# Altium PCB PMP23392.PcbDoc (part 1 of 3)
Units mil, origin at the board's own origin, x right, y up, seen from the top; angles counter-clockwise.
Board outline 5000 x 3400 mil, 6 copper layers (Top Layer, Midlayer 1, Midlayer 2, Midlayer 3, Midlayer 4, Bottom Layer), stack 61.536 mil thick; 247 components, 68 nets, 546 pads, 871 vias.
Unrouted connection lines stored in the file: 21.
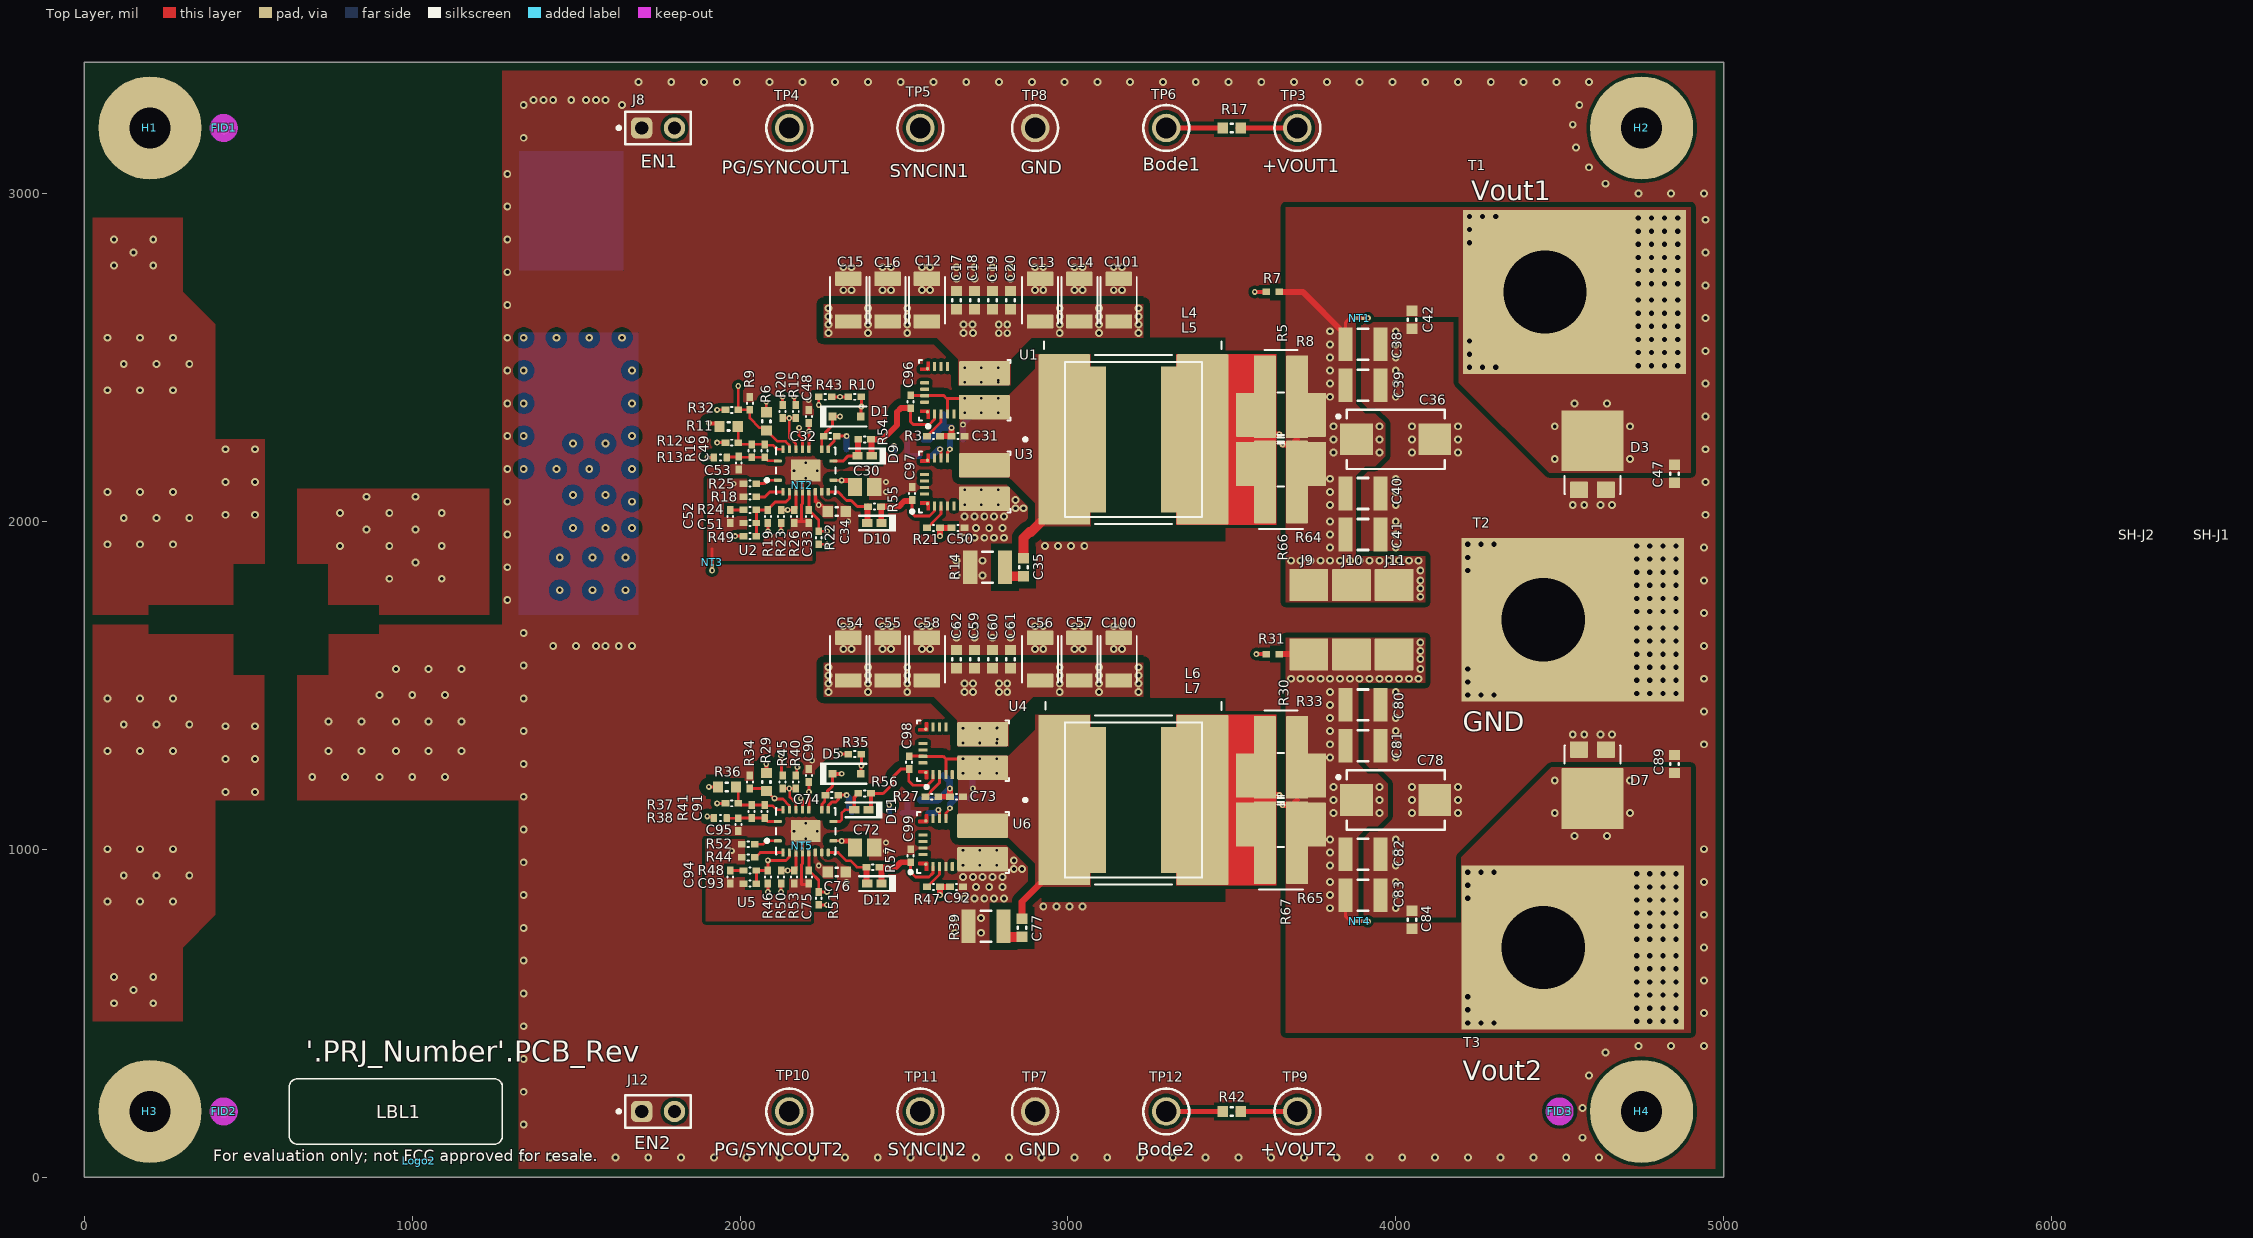
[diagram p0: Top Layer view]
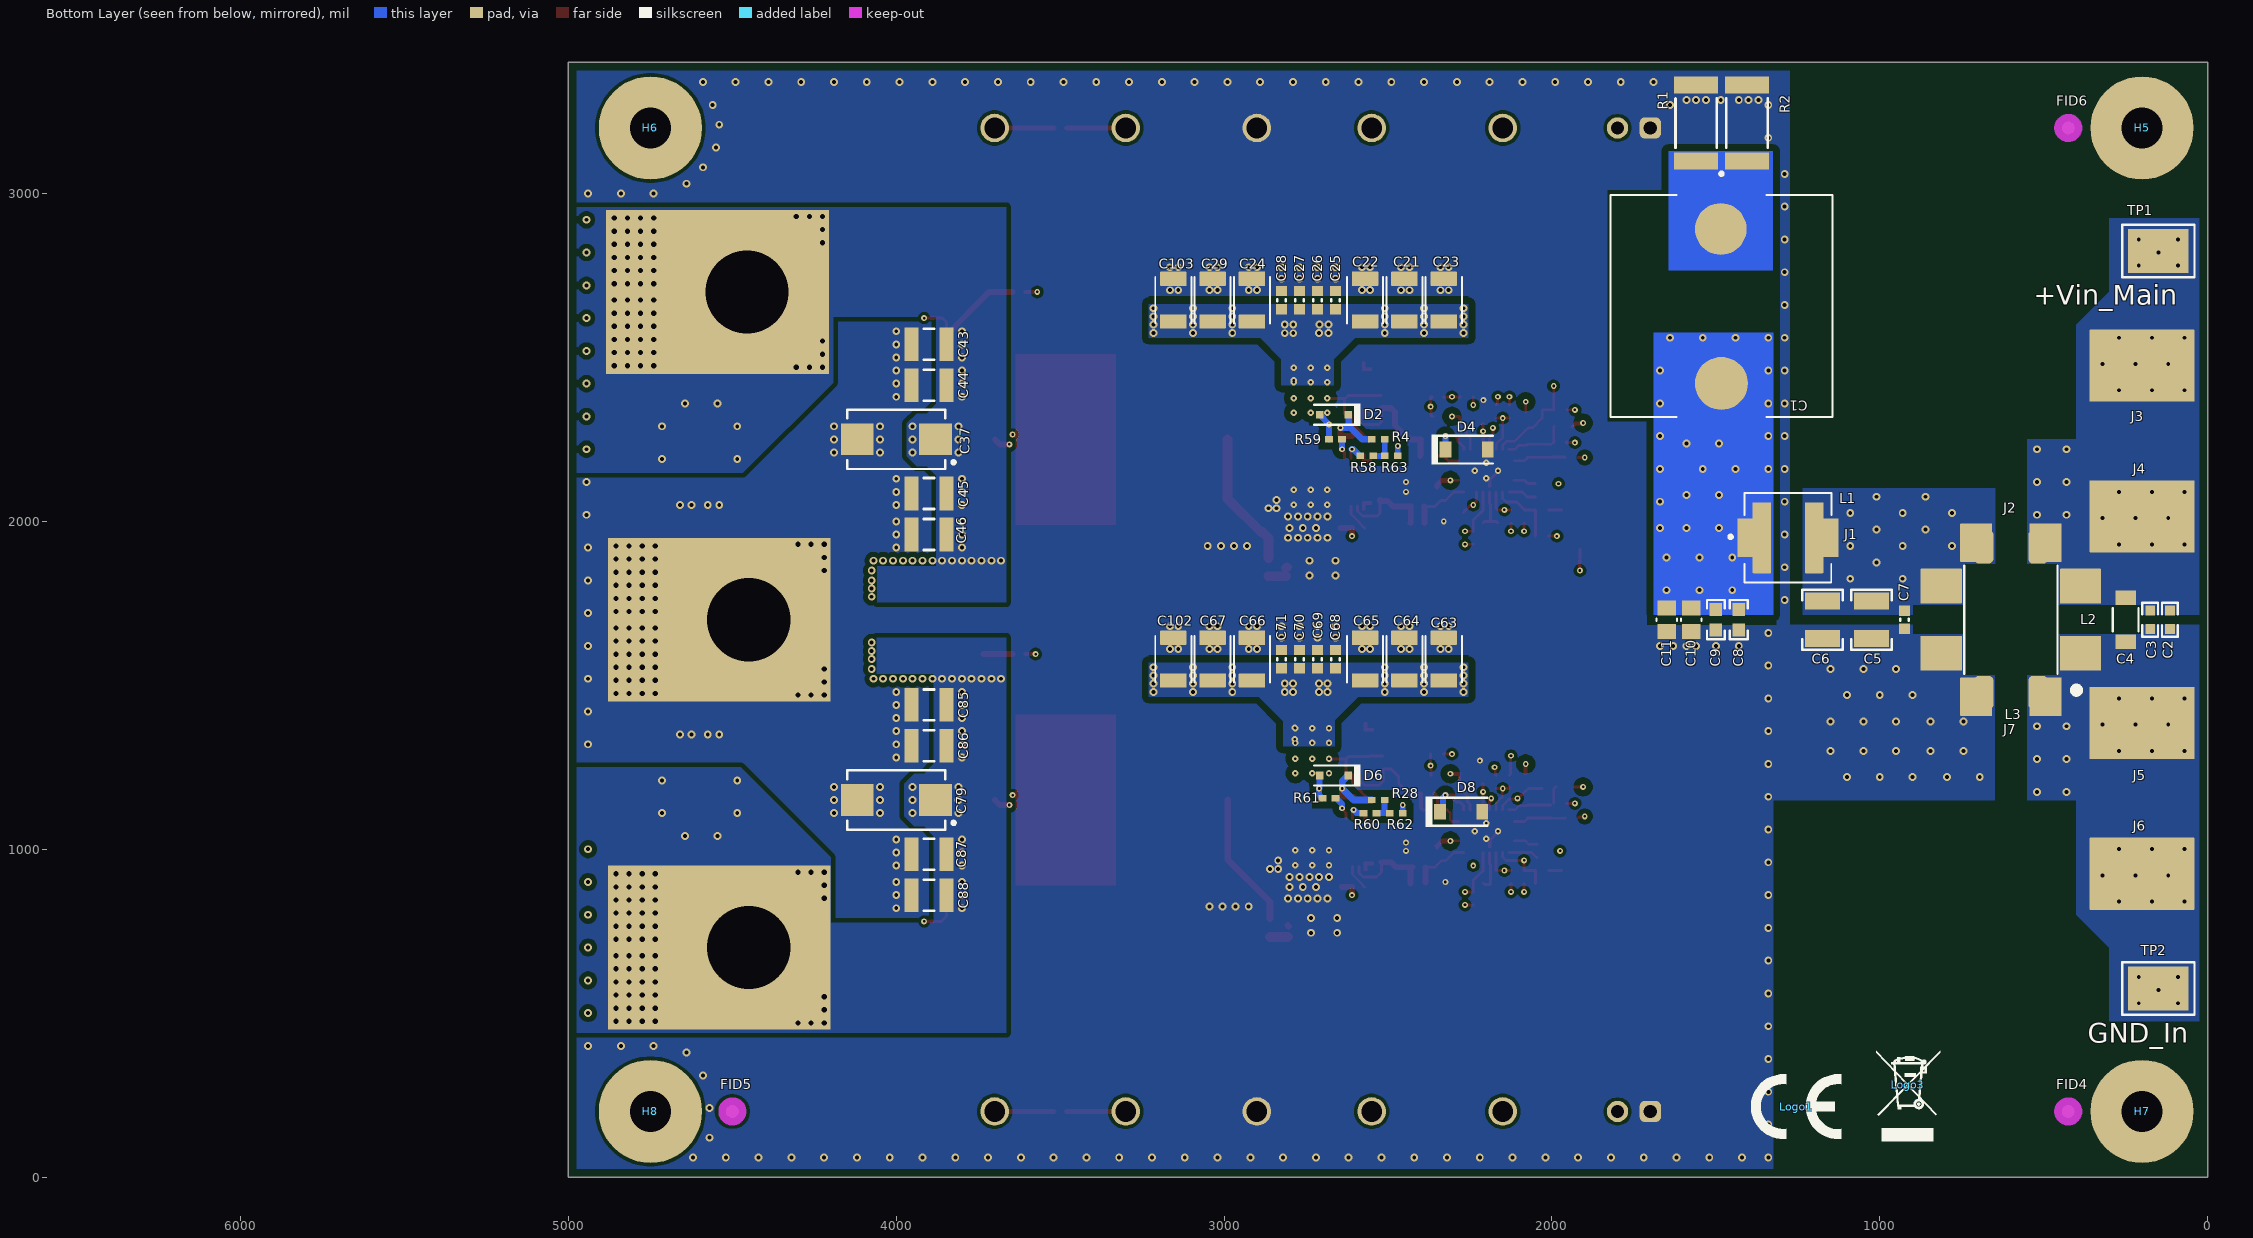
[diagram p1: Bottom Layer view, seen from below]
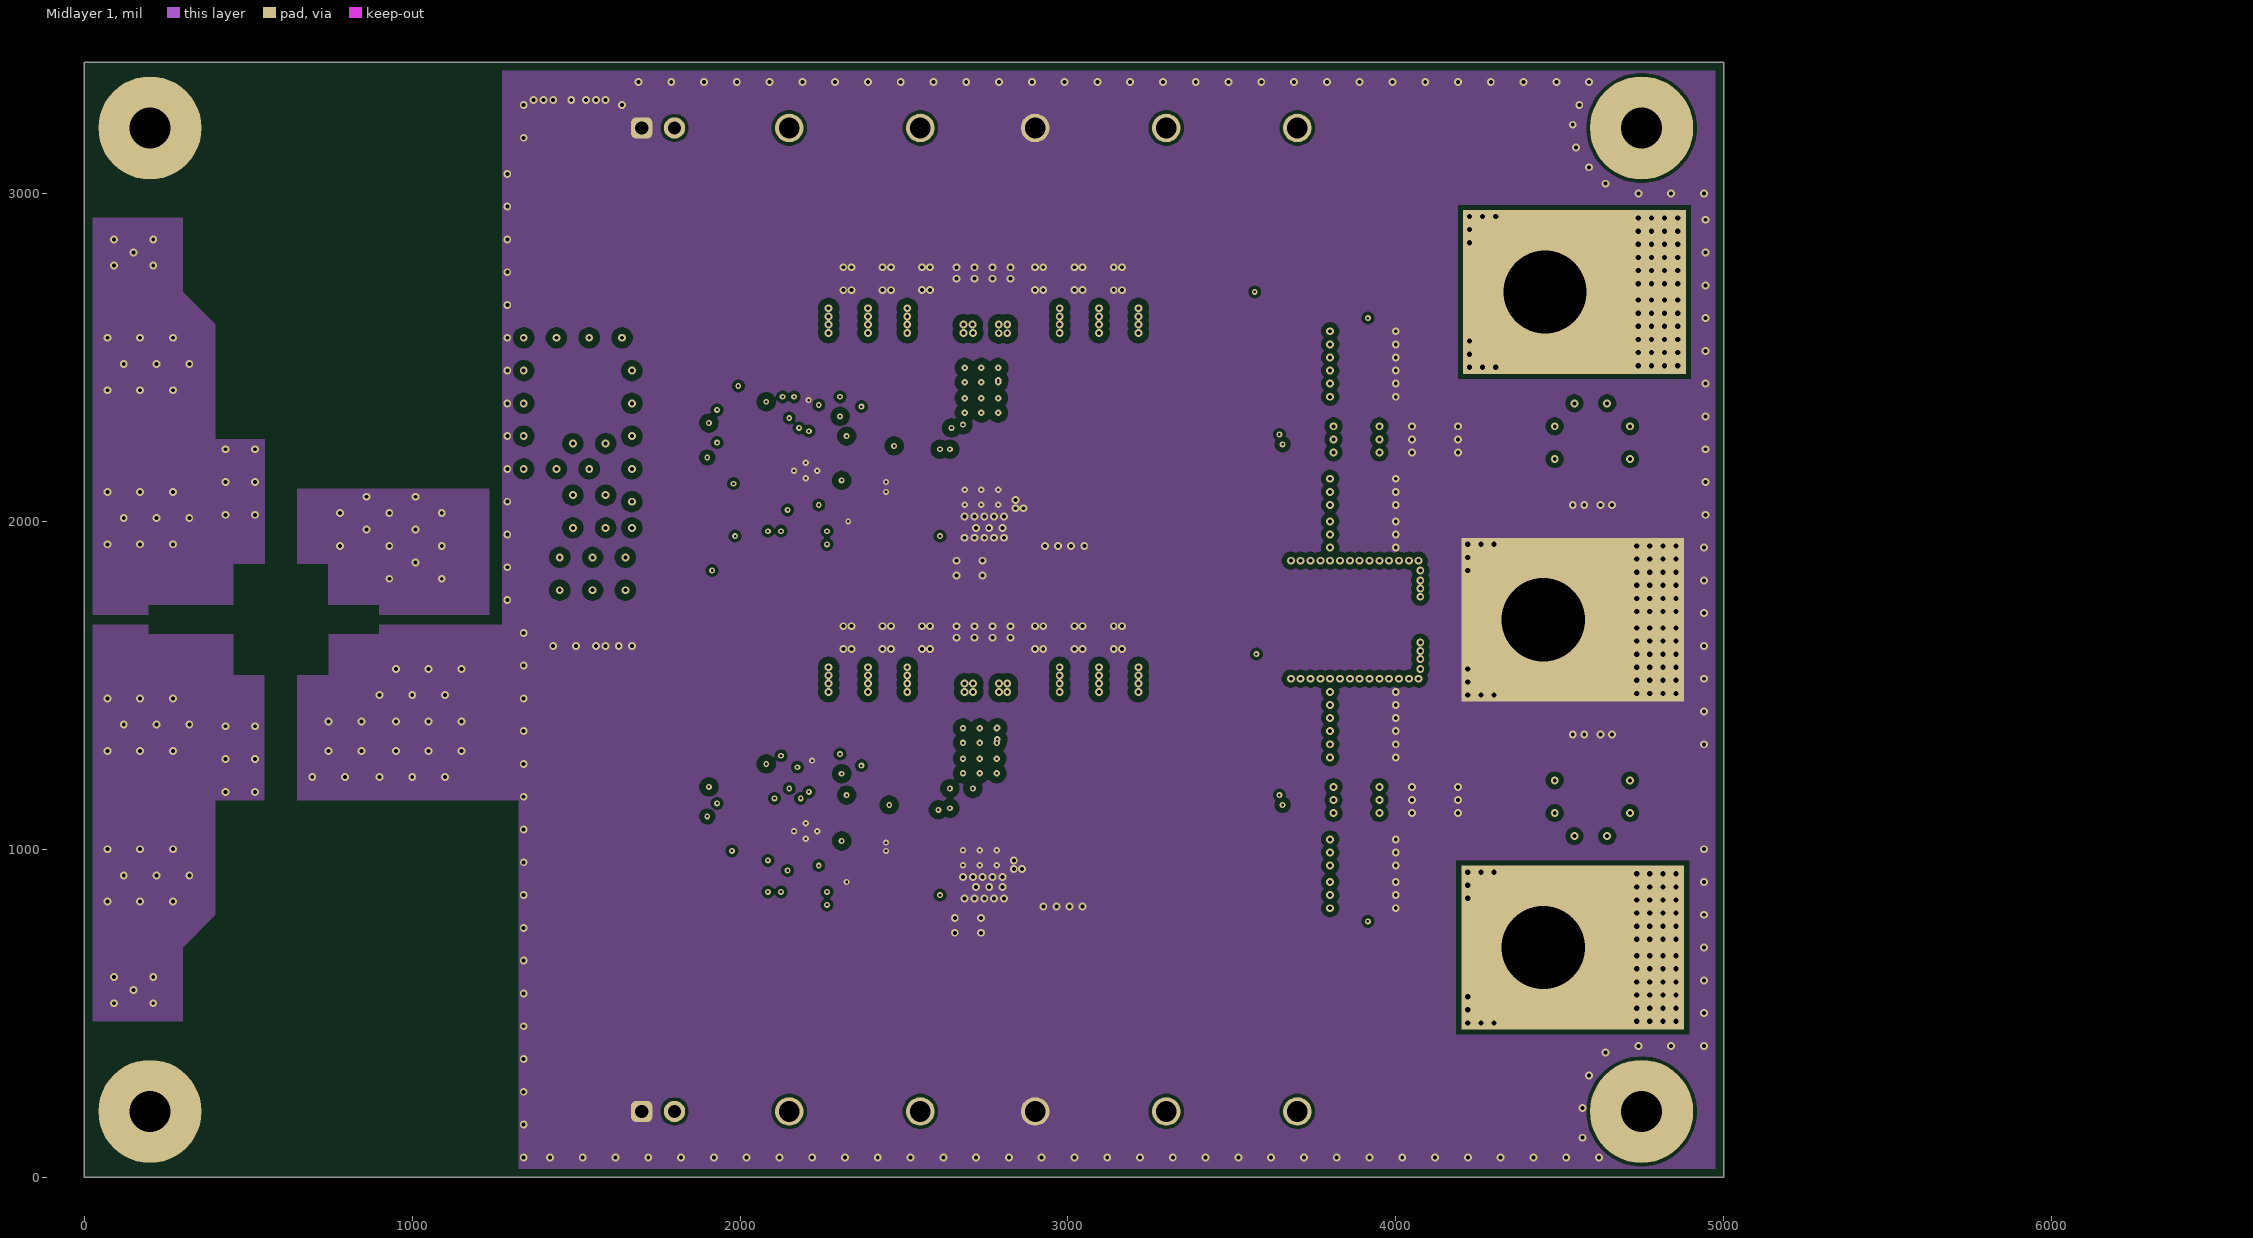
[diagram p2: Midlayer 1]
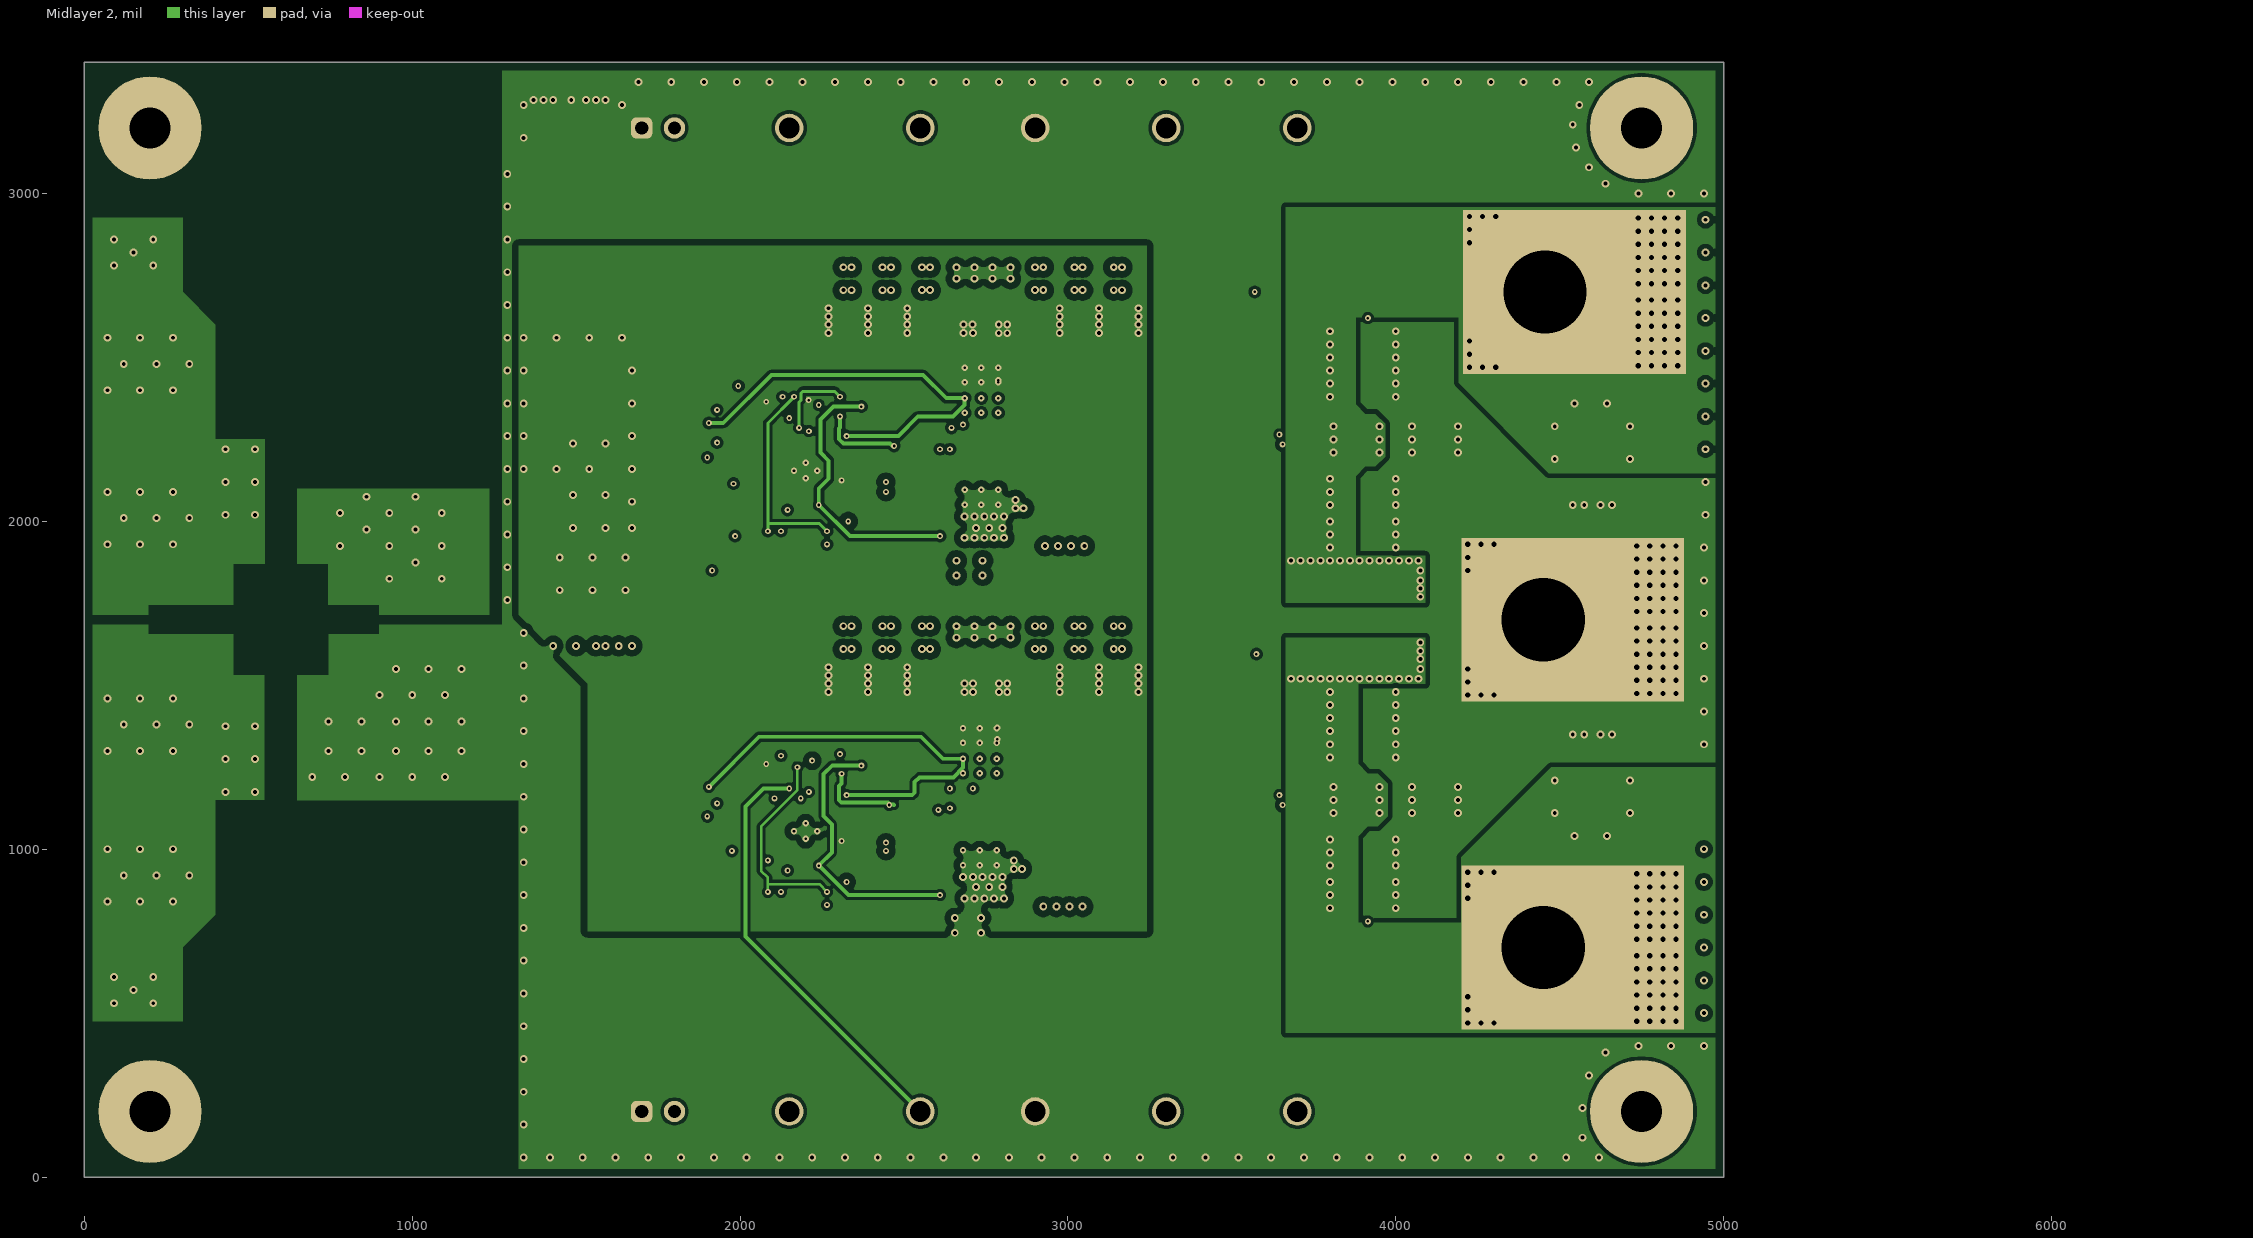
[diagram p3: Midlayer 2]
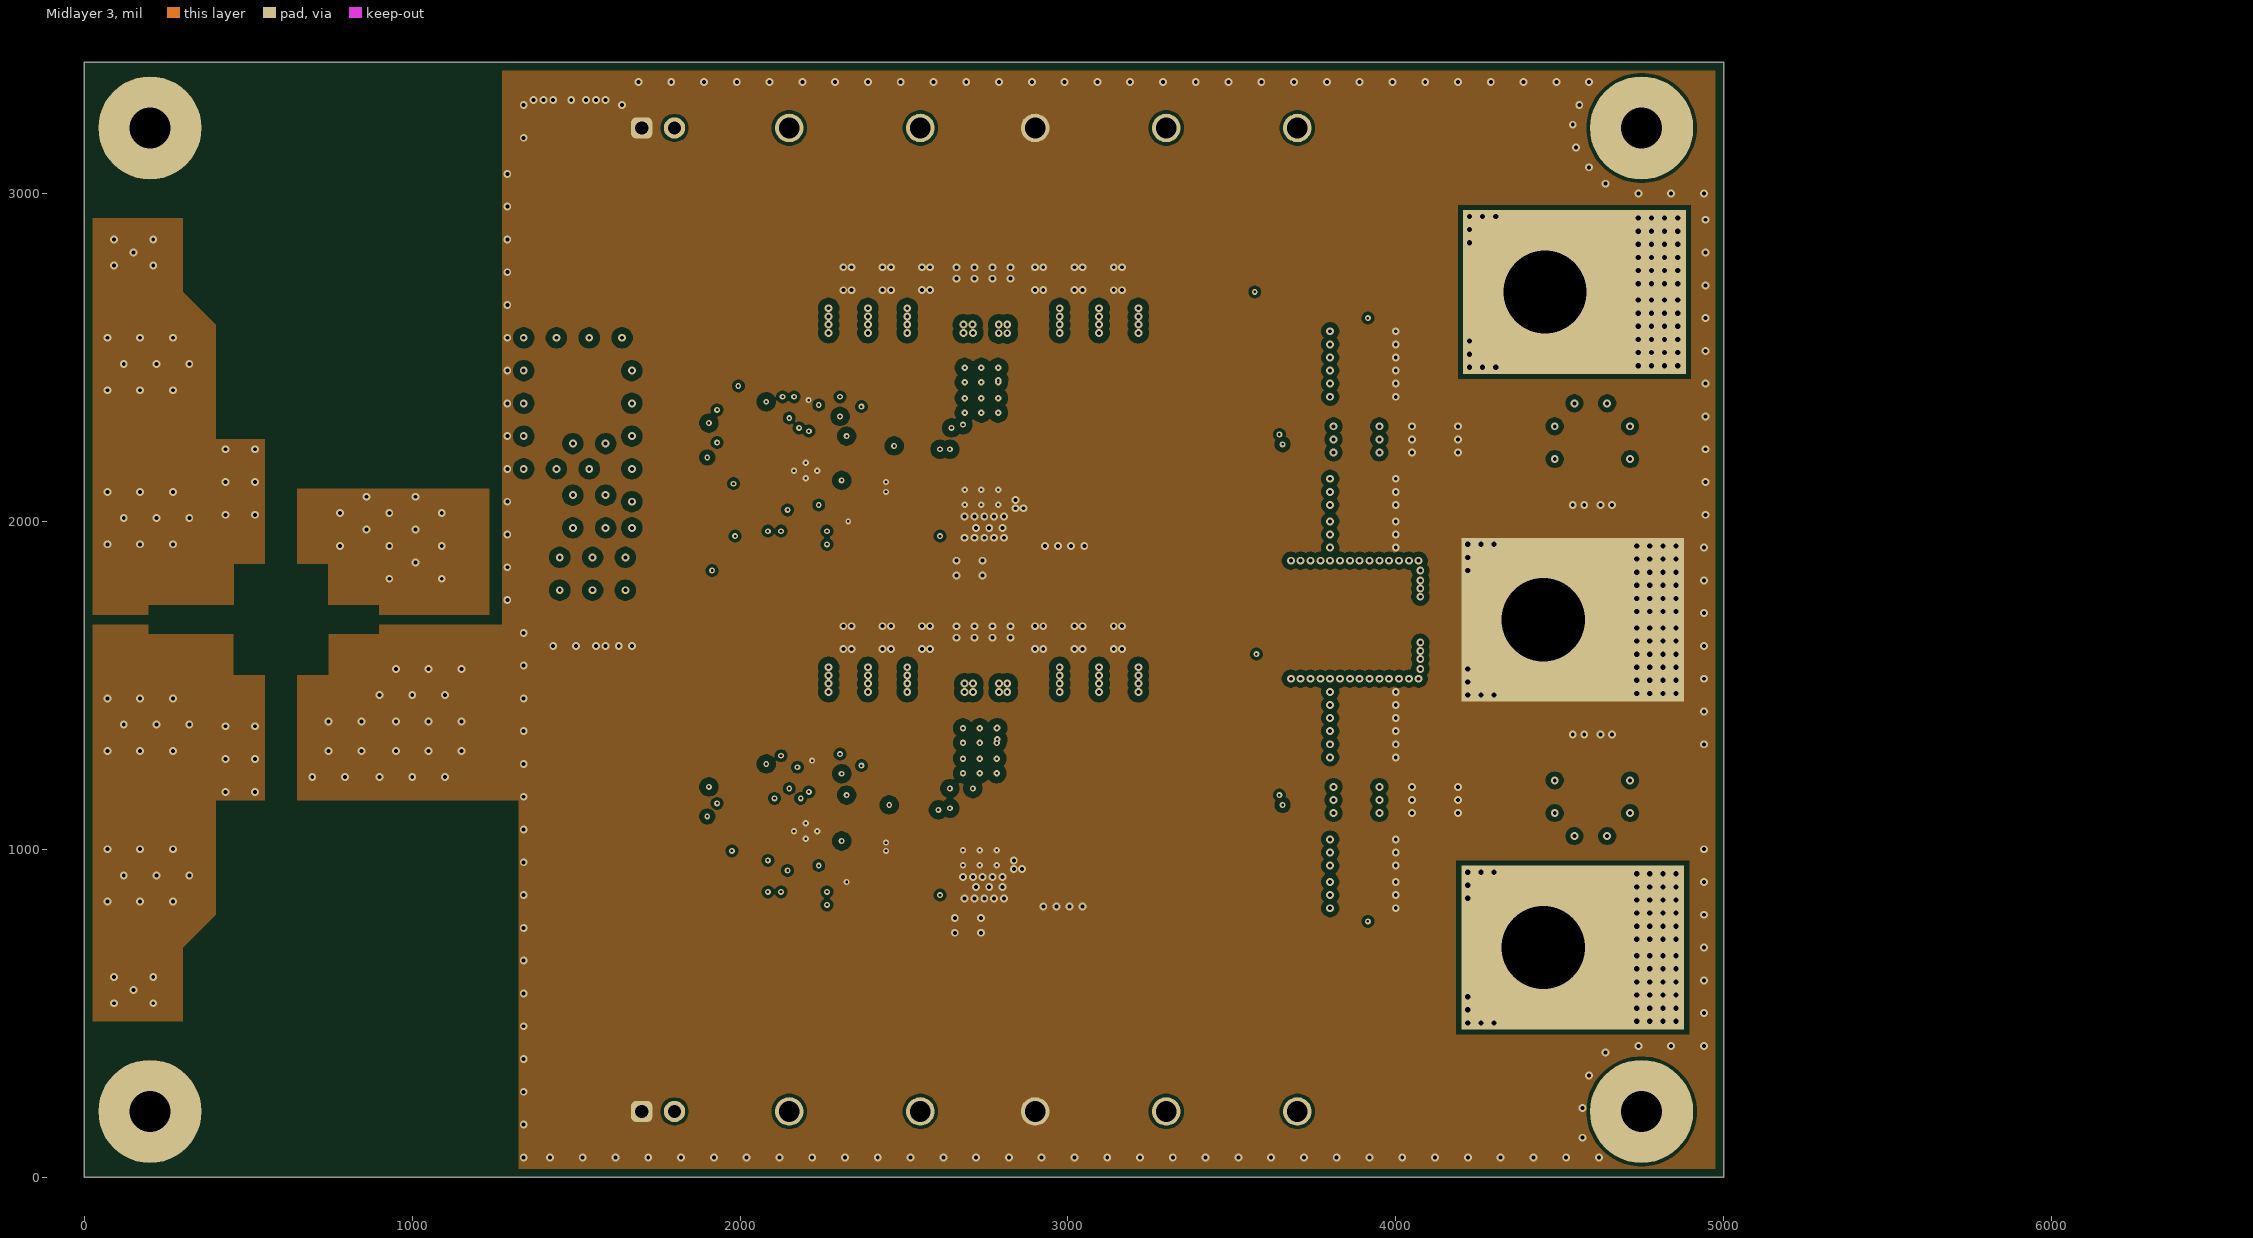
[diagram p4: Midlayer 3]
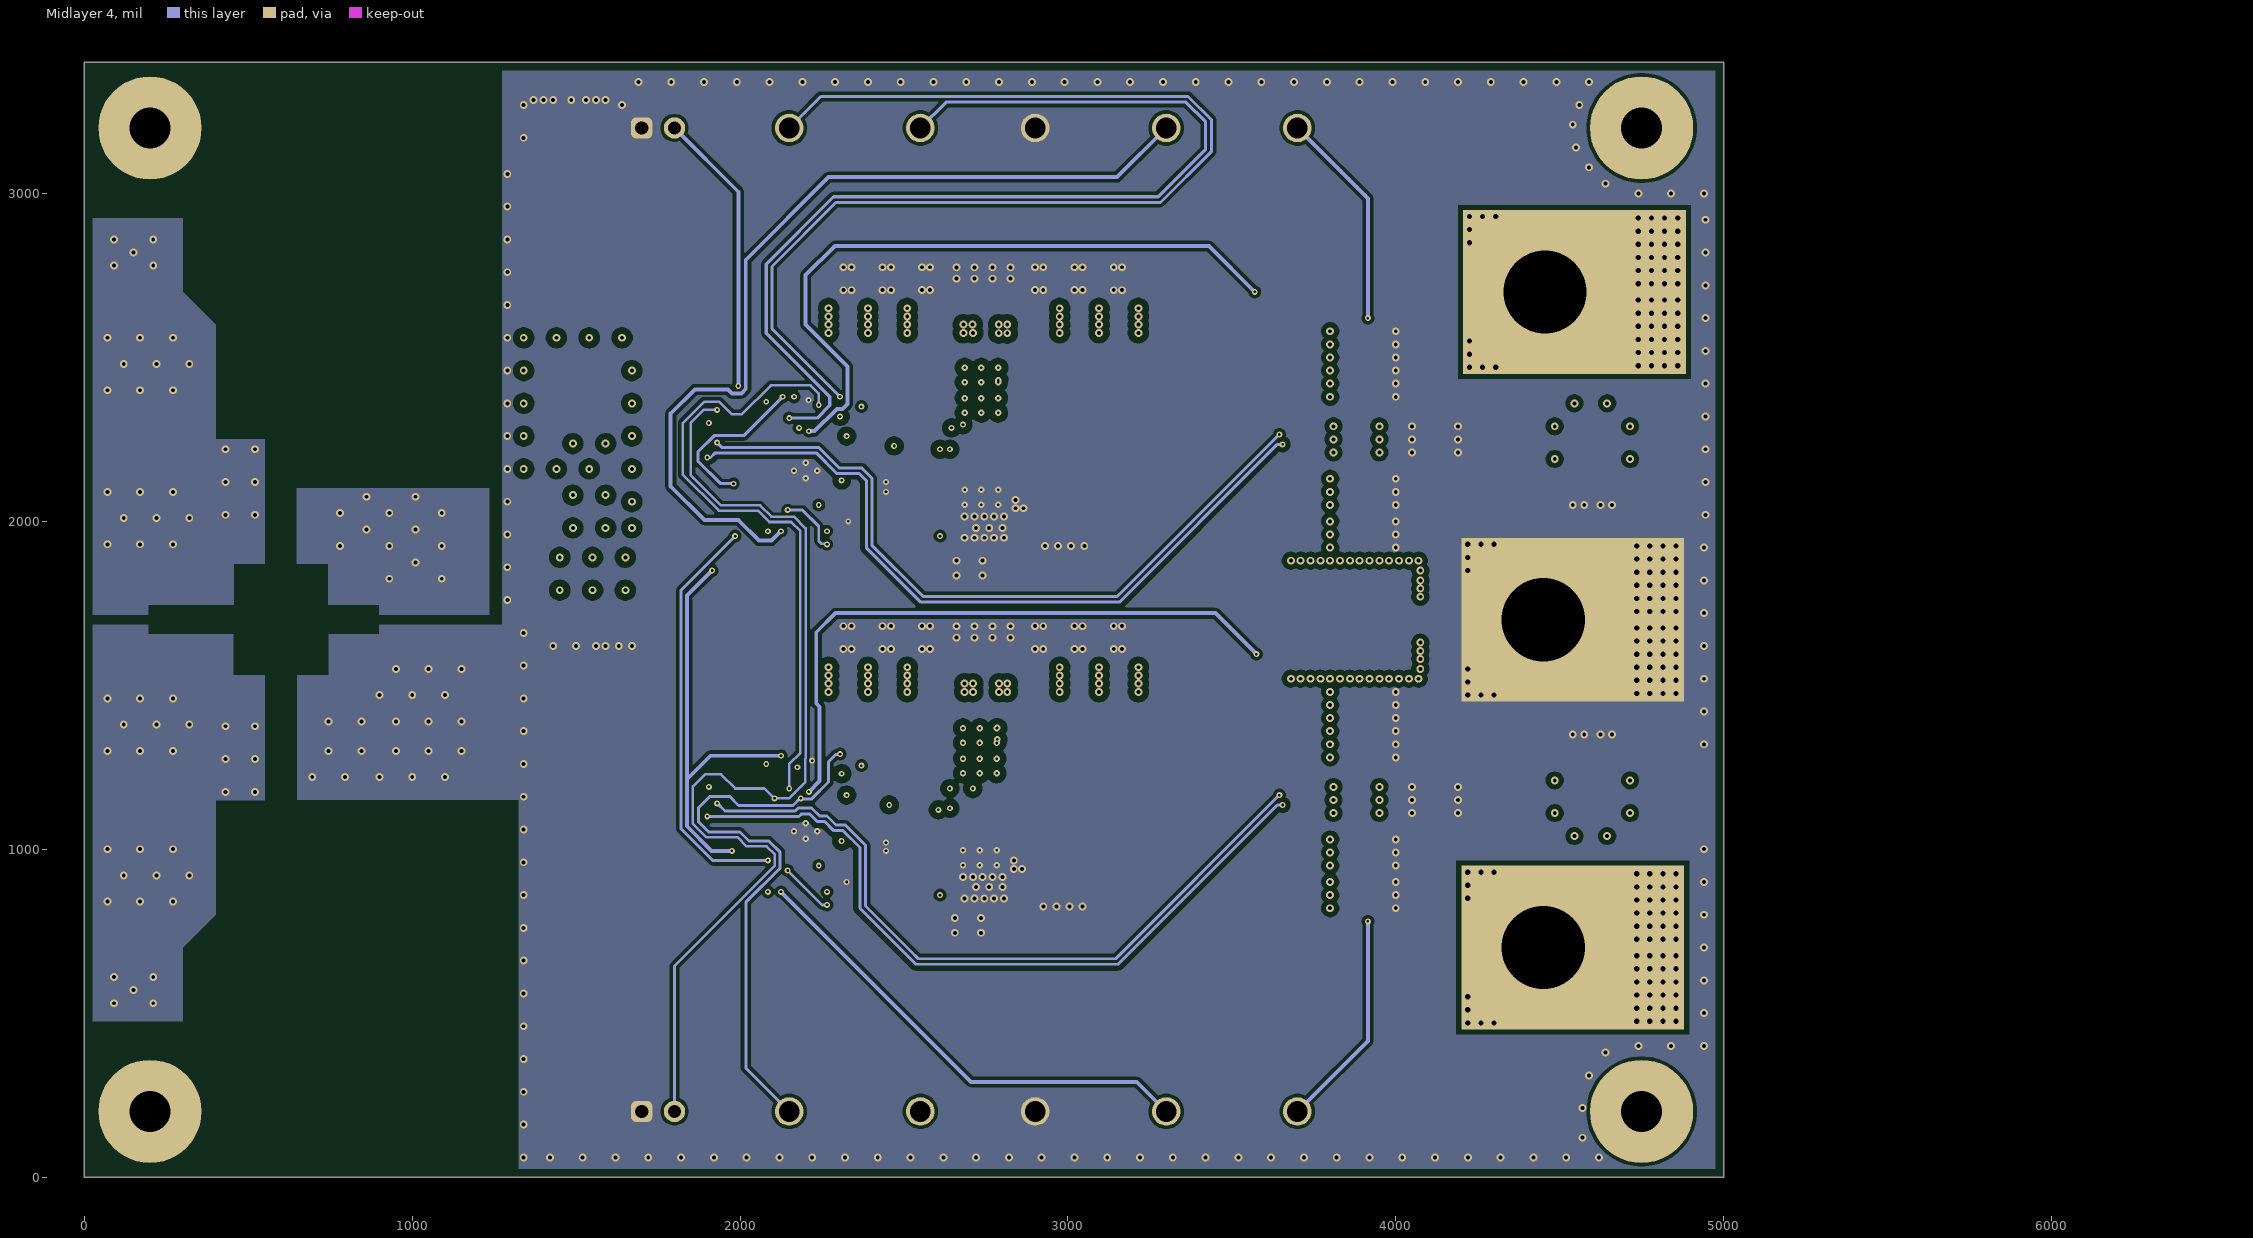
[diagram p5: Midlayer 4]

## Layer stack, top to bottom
Top Solder: solder mask 0.4, Solder Resist, Dk 3.5
Top Layer: signal copper 2.756
Dielectric 1: prepreg 9, PP-023, Dk 4.5
Midlayer 1: signal copper 2.7559
Dielectric 2: prepreg 9, PP-023, Dk 4.5
Midlayer 2: signal copper 2.7559
Dielectric3: core 9, Core-034, Dk 4.6
Midlayer 3: signal copper 2.7559
Dielectric 4: prepreg 9, PP-023, Dk 4.5
Midlayer 4: signal copper 2.7559
Dielectric 5: prepreg 9, PP-023, Dk 4.5
Bottom Layer: signal copper 2.756
Bottom Solder: solder mask 0.4, Solder Resist, Dk 3.5

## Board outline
0,0 5000,0 5000,3400 0,3400

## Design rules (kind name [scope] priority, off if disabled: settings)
AcuteAngle [All] p1: minimum=4.50000000000000E+0001 checktracksonly=FALSE
AssemblyTestPointUsage [All] p1: valid=2
BoardOutlineClearance BoardOutlineClearance_MountingHoles [OnCopper and InComponentClass('Mounting Holes')] p1: gap=39.37 ignorepadtopadclearanceinfootprint=FALSE
BoardOutlineClearance BoardOutlineClearance_Poly [OnCopper and IsPoly] p2: gap=25 ignorepadtopadclearanceinfootprint=FALSE
BoardOutlineClearance [OnCopper and Not InComponentClass('Logo') and not InComponentClass('FiducialMark') and not InRegion(1000,500,4000,800) and not InPoly] p3: gap=40 ignorepadtopadclearanceinfootprint=FALSE
Clearance Clearance_HV [InNetClass('HV') vs InNet('GND')] p1: gap=20 ignorepadtopadclearanceinfootprint=TRUE
Clearance Clearance_VOUT [(InNet('VOUT1') OR InNet('VOUT2')) vs InNet('GND')] p2: gap=15 ignorepadtopadclearanceinfootprint=TRUE
Clearance Clearance_Keepouts [((IsTrack Or IsArc) And Not InPoly) And IsFree and IsKeepOut vs ((IsTrack Or IsArc) And Not InPoly) And IsFree and IsKeepOut] p3: gap=0 ignorepadtopadclearanceinfootprint=FALSE
Clearance Clearance_Poly [InPolygon] p4: gap=10 ignorepadtopadclearanceinfootprint=TRUE
Clearance Clearance_FiducialMark [IsKeepOut and InComponentClass('FiducialMark') vs IsPad and InComponentClass('FiducialMark')] p5: gap=0 ignorepadtopadclearanceinfootprint=FALSE
Clearance [All] p6: gap=7.87 ignorepadtopadclearanceinfootprint=TRUE
ComponentClearance ComponentClearance_L3,J2 [InComponent('L3') vs InComponent('J2')] p1: gap=-1 collisioncheckmode=3 verticalgap=100000 showdistances=FALSE
ComponentClearance "ComponentClearance_L1, J1" [InComponent('L1') vs InComponent('J1')] p2: gap=-1 collisioncheckmode=3 verticalgap=100000 showdistances=FALSE
ComponentClearance "ComponentClearance_L2, J2" [InComponent('L2') vs InComponent('J2')] p3: gap=-1 collisioncheckmode=3 verticalgap=100000 showdistances=FALSE
ComponentClearance "ComponentClearance_L3, J7" [InComponent('L3') vs InComponent('J7')] p4: gap=-1 collisioncheckmode=3 verticalgap=100000 showdistances=FALSE
ComponentClearance "ComponentClearance_L2, J7" [InComponent('L2') vs InComponent('J7')] p5: gap=-1 collisioncheckmode=3 verticalgap=100000 showdistances=FALSE
ComponentClearance "ComponentClearance_L2, J4" [InComponent('L2') vs InComponent('J4')] p6: gap=-1 collisioncheckmode=3 verticalgap=100000 showdistances=FALSE
ComponentClearance ComponentClearance_L2,L3 [InComponent('L2') vs InComponent('L3')] p7: gap=-1 collisioncheckmode=3 verticalgap=100000 showdistances=FALSE
ComponentClearance "ComponentClearance_NT5, U5" [InComponent('NT5') vs InComponent('U5')] p8: gap=-1 collisioncheckmode=3 verticalgap=100000 showdistances=FALSE
ComponentClearance "ComponentClearance_NT2, U2" [InComponent('NT2') vs InComponent('U2')] p9: gap=-1 collisioncheckmode=3 verticalgap=100000 showdistances=FALSE
ComponentClearance ComponentClearance_R5,R8 [InComponent('R5') vs InComponent('R8')] p10: gap=-1 collisioncheckmode=3 verticalgap=100000 showdistances=FALSE
ComponentClearance ComponentClearance_R5,R66 [InComponent('R5') vs InComponent('R66')] p11: gap=-1 collisioncheckmode=3 verticalgap=100000 showdistances=FALSE
ComponentClearance "ComponentClearance_R8, R66" [InComponent('R8') vs InComponent('R66')] p12: gap=-1 collisioncheckmode=3 verticalgap=100000 showdistances=FALSE
ComponentClearance ComponentClearance_R5,R64 [InComponent('R5') vs InComponent('R64')] p13: gap=-1 collisioncheckmode=3 verticalgap=100000 showdistances=FALSE
ComponentClearance "ComponentClearance_R64, R66" [InComponent('R64') vs InComponent('R66')] p14: gap=-1 collisioncheckmode=3 verticalgap=100000 showdistances=FALSE
ComponentClearance "ComponentClearance_L4, L5" [(InComponent('L4') OR InComponent('L5'))] p15: gap=-1 collisioncheckmode=3 verticalgap=100000 showdistances=FALSE
ComponentClearance "ComponentClearance_L6, L7" [(InComponent('L6') OR InComponent('L7'))] p16: gap=-1 collisioncheckmode=3 verticalgap=100000 showdistances=FALSE
ComponentClearance ComponentClearance_R30,R33 [InComponent('R30') vs InComponent('R33')] p17: gap=-1 collisioncheckmode=3 verticalgap=100000 showdistances=FALSE
ComponentClearance "ComponentClearance_R33, R67" [InComponent('R33') vs InComponent('R67')] p18: gap=-1 collisioncheckmode=3 verticalgap=100000 showdistances=FALSE
ComponentClearance ComponentClearance_R30,R65 [InComponent('R30') vs InComponent('R65')] p19: gap=-1 collisioncheckmode=3 verticalgap=100000 showdistances=FALSE
ComponentClearance ComponentClearance_R30,R67 [InComponent('R30') vs InComponent('R67')] p20: gap=-1 collisioncheckmode=3 verticalgap=100000 showdistances=FALSE
ComponentClearance "ComponentClearance_R65, R67" [InComponent('R65') vs InComponent('R67')] p21: gap=-1 collisioncheckmode=3 verticalgap=100000 showdistances=FALSE
ComponentClearance ComponentClearance_MountingHoles_FiducialMarks [InComponentClass('Mounting Holes') vs InComponentClass('FiducialMark')] p22: gap=50 collisioncheckmode=3 verticalgap=10 showdistances=FALSE
ComponentClearance ComponentClearance_Shunt [InComponentClass('Header') vs InComponentClass('Shunt')] p23: gap=0 collisioncheckmode=3 verticalgap=0 showdistances=FALSE
ComponentClearance ComponentClearance_Logo [InComponentClass('Logo')] p24: gap=30 collisioncheckmode=3 verticalgap=10 showdistances=FALSE
ComponentClearance ComponentClearance_ScrewToNut [(HasFootprint('NY PMS 440 0025 PH')) vs (HasFootprint('Keystone_1902C'))] p25: gap=5 collisioncheckmode=3 verticalgap=10 showdistances=FALSE
ComponentClearance ComponentClearance_MountingHoles [InComponentClass('Mounting Holes')] p26: gap=100 collisioncheckmode=3 verticalgap=100000 showdistances=FALSE
ComponentClearance ComponentClearance_SmallPassives [HasFootprint('0201*') or HasFootprint('0402*') or HasFootprint('0508') or HasFootprint('0603*') or HasFootprint('0612') or HasFootprint('0805*') or HasFootprint('0815*') or HasFootprint('0830*') or HasFootprint('1206*') or HasFootprint('1210*') or HasFootprint('1808*') or HasFootprint('1812*') or HasFootprint('1825*') or HasFootprint('2010*') or HasFootprint('2220*') or HasFootprint('2225*') or HasFootprint('2512*') or HasFootprint('2728*') or HasFootprint('3518*') vs HasFootprint('0201*') or HasFootprint('0402*') or HasFootprint('0508') or HasFootprint('0603*') or HasFootprint('0612') or HasFootprint('0805*') or HasFootprint('0815*') or HasFootprint('0830*') or HasFootprint('1206*') or HasFootprint('1210*') or HasFootprint('1808*') or HasFootprint('1812*') or HasFootprint('1825*') or HasFootprint('2010*') or HasFootprint('2220*') or HasFootprint('2225*') or HasFootprint('2512*') or HasFootprint('2728*') or HasFootprint('3518*')] p27: gap=14.96 collisioncheckmode=3 verticalgap=10 showdistances=FALSE
ComponentClearance ComponentClearance_THtoSMT [IsThruComponent vs IsSMTComponent] p28: gap=30 collisioncheckmode=3 verticalgap=30 showdistances=FALSE
ComponentClearance ComponentClearance_THtoTH [IsThruComponent vs IsThruComponent] p29: gap=20 collisioncheckmode=3 verticalgap=30 showdistances=FALSE
ComponentClearance [All] p30: gap=20 collisioncheckmode=3 verticalgap=10 showdistances=FALSE
DiffPairsRouting [All] p1: maxlimit=100 minlimit=10 mostfreqgap=10 toplayer_minwidth=15 toplayer_maxwidth=15 toplayer_prefwidth=15 midlayer1_minwidth=15 midlayer1_maxwidth=15 midlayer1_prefwidth=15 midlayer2_minwidth=15 midlayer2_maxwidth=15 midlayer2_prefwidth=15 midlayer3_minwidth=15 midlayer3_maxwidth=15 midlayer3_prefwidth=15 midlayer4_minwidth=15 midlayer4_maxwidth=15 midlayer4_prefwidth=15 bottomlayer_minwidth=15 bottomlayer_maxwidth=15 bottomlayer_prefwidth=15 maxuncoupledlength=1000
FabricationTestPointUsage TestPointUsage [All] p1: valid=2 allowmultiple=FALSE
FabricationTestpoint Testpoint [All] p1: side=3 testpointundercomponent=TRUE minsize=40 maxsize=100 preferedsize=60 minholesize=0 maxholesize=40 preferedholesize=32 testpointgrid=1 allowsidetop=TRUE allowsidebottom=TRUE usegrid=TRUE gridtolerance=0.01
FanoutControl Fanout_LCC [IsLCC] p1: bgadir=Out bgaviamode=Centered fanoutstyle=Auto fanoutdirection=Alternating viagrid=1 // Fanout_LCC (Default Rule)
FanoutControl Fanout_BGA [IsBGA] p2: bgadir=Out bgaviamode=Centered fanoutstyle=Auto fanoutdirection=Alternating viagrid=1 // Fanout_BGA (Default Rule)
FanoutControl Fanout_Default [All] p4: bgadir=Out bgaviamode=Centered fanoutstyle=Auto fanoutdirection=Alternating viagrid=1 // Fanout_Default (Default Rule)
FanoutControl Fanout_Small [(CompPinCount < 5)] p5: bgadir=Out bgaviamode=Centered fanoutstyle=Auto fanoutdirection=OutThenIn viagrid=1 // Fanout_Small (Default Rule)
HoleSize [All] p1: absolutevalues=TRUE maxlimit=255 minlimit=7.87 maxpercent=80.000 minpercent=20.000
MinimumAnnularRing MinimumAnnularRing_ThermalPadVias [IsVia and InAnyComponent] p1: minimumring=5.91
MinimumAnnularRing [All] p2: minimumring=5
MinimumSolderMaskSliver MinimumSolderMaskSliver_Logo [InComponentClass('Logo') vs InComponentClass('Logo')] p1: minsoldermaskwidth=0.7
MinimumSolderMaskSliver [All] p2: minsoldermaskwidth=3.94
PlaneConnect [All] p1: planeconnectstyle=Direct reliefexpansion=10 reliefentries=4 reliefconductorwidth=10 reliefairgap=10
PolygonConnect [All] p1: connectstyle=Direct reliefconductorwidth=10 reliefentries=4 polygonreliefangle="90 Angle" airgapwidth=10
RoutingVias ThermalPadVias [IsVia and InAnyComponent] p1: holewidth=7.87 width=19.68 viastyle="Through Hole" minholewidth=7.87 minwidth=18 maxholewidth=40 maxwidth=50
RoutingVias [All] p2: holewidth=16 width=34 viastyle="Through Hole" minholewidth=7.87 minwidth=18 maxholewidth=40 maxwidth=65
SilkToBoardRegionClearance [Not ((IsComment or IsDesignator) And (Hide <> 'False')) and not InRegion(1000,500,4000,800)] p1:
SilkToSilkClearance SilkToSilkClearance_Pb-FreeLogo [(HasFootprint('Pb-Free_Overlay_Medium') OR HasFootprint('Pb-Free_Overlay_Small')) vs (HasFootprint('Pb-Free_Overlay_Medium') OR HasFootprint('Pb-Free_Overlay_Small'))] p1: silktosilkclearance=0
SilkToSilkClearance [All] p2: silktosilkclearance=1
SilkToSolderMaskClearance SilkToComponentPadClearance [(IsPad or IsFill or IsRegion) and InAnycomponent] p1: minsilkscreentomaskgap=2 clearancetoexposedcopper=TRUE
SilkToSolderMaskClearance "Silk to Solder Mask Opening" [All] p2: minsilkscreentomaskgap=2 clearancetoexposedcopper=FALSE
SolderMaskExpansion [All] p1: expansion=1.97 istentingtop=FALSE
UnRoutedNet [All] p1: checkbadconnections=TRUE
Width [All] p1: maxlimit=100 minlimit=6 preferedwidth=10 checkconnectedcopper=TRUE
14 further rules are at their usual default settings.

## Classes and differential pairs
net class HV: +Filter +Vin_Main HO1 HO1_GAN HO2 HO2_GAN NetC1_1 NetC31_1 NetC35_2 NetC73_1 NetC77_2 NetR3_2 NetR4_2 NetR27_2 NetR28_2 NetR58_1 NetR59_1 NetR60_1 NetR61_1 SW1 SW2 Vbst1 Vbst2 VIN
component class Shunt: SH-J1 SH-J2
component class PMP23392_BlankSheet: C1 C2 C3 C4 C5 C6 C7 C8 C9 C10 C11 C12 C13 C14 C15 C16 C17 C18 C19 C20 C21 C22 C23 C24 C25 C26 C27 C28 C29 C30 C31 C32 C33 C34 C35 C36 C37 C38 C39 C40 C41 C42 C43 C44 C45 C46 C47 C48 C49 C50 C51 C52 C53 C54 C55 C56 C57 C58 C59 C60 C61 C62 C63 C64 C65 C66 C67 C68 C69 C70 C71 C72 C73 C74 C75 C76 C77 C78 C79 C80 C81 C82 C83 C84 C85 C86 C87 C88 C89 C90 C91 C92 C93 C94 C95 C96 C97 C98 C99 C100 C101 C102 C103 D1 D2 D3 D4 D5 D6 D7 D8 D9 D10 D11 D12 J1 J2 J3 J4 J5 J6 J7 J8 J9 J10 J11 J12 L1 L2 L3 L4 L5 L6 L7 NT1 NT2 NT3 NT4 NT5 R1 R2 R3 R4 R5 R6 R7 R8 R9 R10 R11 R12 R13 R14 R15 R16 R17 R18 R19 R20 R21 R22 R23 R24 R25 R26 R27 R28 R29 R30 R31 R32 R33 R34 R35 R36 R37 R38 R39 R40 R41 R42 R43 R44 R45 R46 R47 R48 R49 R50 R51 R52 R53 R54 R55 R56 R57 R58 R59 R60 R61 R62 R63 R64 R65 R66 R67 SH-J1 SH-J2 T1 T2 T3 TP1 TP2 TP3 TP4 TP5 TP6 TP7 TP8 TP9 TP10 TP11 TP12 U1 U2 U3 U4 U5 U6
component class Header: J8 J12
component class Label: LBL1
component class FiducialMark: FID1 FID2 FID3 FID4 FID5 FID6
component class PMP23392_Hardware: FID1 FID2 FID3 FID4 FID5 FID6 H1 H2 H3 H4 H5 H6 H7 H8 LBL1 Logo1 Logo2 Logo3
component class "Mounting Holes": H1 H2 H3 H4

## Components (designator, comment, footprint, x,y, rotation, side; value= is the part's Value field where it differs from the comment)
C1 "EEE-TP1K391V" FP-EEE-TP1K391V_SMT_CAP_17MM0_17MM0-MFG 1483,2657 r270 bottom value=390µF
C2 "GCM188R72A103KA37J" 0603_HV 115,1700 r270 bottom value=0.01uF
C3 "GCM188R72A103KA37J" 0603_HV 175,1700 r270 bottom value=0.01uF
C4 "CGA5L3X7S2A225K160AB" 1206_180 250,1700 r270 bottom value=2.2uF
C5 "C3225X7S2A475K200AB" 1210_220 1025,1700 r90 bottom value=4.7uF
C6 "CGA6M3X7S2A475K200AB" 1210_220 1175,1700 r90 bottom value=4.7uF
C7 "GCM188R72A103KA37J" 0603L 925,1700 r270 bottom value=0.01uF
C8 "GCM188R72A103KA37J" 0603 1430,1700 r270 bottom value=0.01uF
C9 "GCM188R72A103KA37J" 0603 1500,1700 r270 bottom value=0.01uF
C10 "08051C105K4Z2A" 0805_150 1575,1700 r270 bottom value=1uF
C11 "08051C105K4Z2A" 0805_150 1650,1700 r270 bottom value=1uF
C12 "GCJ32DC72A475KE01L" FP-GCJ32DC72A475KE01L_1210-MFG 2570,2675 r270 top value=4.7µF
C13 "GCJ32DC72A475KE01L" FP-GCJ32DC72A475KE01L_1210-MFG 2915,2675 r270 top value=4.7µF
C14 "GCJ32DC72A475KE01L" FP-GCJ32DC72A475KE01L_1210-MFG 3035,2675 r270 top value=4.7µF
C15 "GCJ32DC72A475KE01L" FP-GCJ32DC72A475KE01L_1210-MFG 2330,2675 r270 top value=4.7µF
C16 "GCJ32DC72A475KE01L" FP-GCJ32DC72A475KE01L_1210-MFG 2450,2675 r270 top value=4.7µF
C17 "GCJ188R72A104KA01D" 0603L 2660,2675 r90 top value=0.1uF
C18 "GCJ188R72A104KA01D" 0603L 2715,2675 r90 top value=0.1uF
C19 "GCJ188R72A104KA01D" 0603L 2770,2675 r90 top value=0.1uF
C20 "GCJ188R72A104KA01D" 0603L 2825,2675 r90 top value=0.1uF
C21 "DNP" FP-GCJ32DC72A475KE01L_1210-MFG 2450,2675 r270 bottom value=4.7µF
C22 "DNP" FP-GCJ32DC72A475KE01L_1210-MFG 2570,2675 r270 bottom value=4.7µF
C23 "DNP" FP-GCJ32DC72A475KE01L_1210-MFG 2330,2675 r270 bottom value=4.7µF
C24 "DNP" FP-GCJ32DC72A475KE01L_1210-MFG 2915,2675 r270 bottom value=4.7µF
C25 "DNP" 0603L 2660,2675 r90 bottom value=0.1uF
C26 "DNP" 0603L 2715,2675 r90 bottom value=0.1uF
C27 "DNP" 0603L 2770,2675 r90 bottom value=0.1uF
C28 "DNP" 0603L 2825,2675 r90 bottom value=0.1uF
C29 "DNP" FP-GCJ32DC72A475KE01L_1210-MFG 3035,2675 r270 bottom value=4.7µF
C30 "KAF21KR72A474KU" 0805L 2380,2105 r0 top value=0.47uF
C31 "GRM155R71H103KA88D" 0402L 2665,2260 r0 top value=0.01uF
C32 "GRM155R71H103KA88D" 0402L 2275,2260 r0 top value=0.01uF
C33 "C0402C104K8RACAUTO" 0402L 2210,2015 r90 top value=0.1uF
C34 "GRM188Z71A475ME15D" 0603L 2295,2030 r0 top value=4.7uF
C35 "DNP" 0603L 2865,1860 r270 top value=330pF
C36 "" 7343-31 4000,2250 r0 top value=220uF
C37 "" 7343-31 4000,2250 r0 bottom value=220uF
C38 "GRT32EC70J107ME13K" 1210L 3900,2540 r0 top value=100uF
C39 "GRT32EC70J107ME13K" 1210L 3900,2415 r0 top value=100uF
C40 "GRT32EC70J107ME13K" 1210L 3900,2085 r0 top value=100uF
C41 "GRT32EC70J107ME13K" 1210L 3900,1960 r0 top value=100uF
C42 "C0603C104K5RACTU" 0603L 4050,2615 r270 top value=0.1uF
C43 "GRT32EC70J107ME13K" 1210L 3900,2540 r0 bottom value=100uF
C44 "GRT32EC70J107ME13K" 1210L 3900,2415 r0 bottom value=100uF
C45 "GRT32EC70J107ME13K" 1210L 3900,2085 r0 bottom value=100uF
C46 "GRT32EC70J107ME13K" 1210L 3900,1960 r0 bottom value=100uF
C47 "Capacitor" 0603L 4850,2145 r270 top value=0.1uF
C48 "C0402C104K8RACAUTO" 0402L 2210,2320 r270 top value=0.1uF
C49 "CGA2B1X7R1E333K050BC" 0402L 2075,2215 r90 top value=0.033uF
C50 "CGA2B1X7R1V224K050BC" 0402L 2665,1980 r0 top value=0.22uF
C51 "CGA2B2NP01H220J050BA" 0402L 2030,1995 r180 top value=22pF
C52 "GCM155R71E223KA55D" 0402L 1970,2015 r270 top value=0.022uF
C53 "GRM155R72A271KA01D" 0402L 1996,2178 r90 top value=270pF
C54 "GCJ32DC72A475KE01L" FP-GCJ32DC72A475KE01L_1210-MFG 2330,1580 r270 top value=4.7µF
C55 "GCJ32DC72A475KE01L" FP-GCJ32DC72A475KE01L_1210-MFG 2450,1580 r270 top value=4.7µF
C56 "GCJ32DC72A475KE01L" FP-GCJ32DC72A475KE01L_1210-MFG 2915,1580 r270 top value=4.7µF
C57 "GCJ32DC72A475KE01L" FP-GCJ32DC72A475KE01L_1210-MFG 3035,1580 r270 top value=4.7µF
C58 "GCJ32DC72A475KE01L" FP-GCJ32DC72A475KE01L_1210-MFG 2570,1580 r270 top value=4.7µF
C59 "GCJ188R72A104KA01D" 0603L 2715,1580 r90 top value=0.1uF
C60 "GCJ188R72A104KA01D" 0603L 2770,1580 r90 top value=0.1uF
C61 "GCJ188R72A104KA01D" 0603L 2825,1580 r90 top value=0.1uF
C62 "GCJ188R72A104KA01D" 0603L 2660,1580 r90 top value=0.1uF
C63 "DNP" FP-GCJ32DC72A475KE01L_1210-MFG 2330,1580 r270 bottom value=4.7µF
C64 "DNP" FP-GCJ32DC72A475KE01L_1210-MFG 2450,1580 r270 bottom value=4.7µF
C65 "DNP" FP-GCJ32DC72A475KE01L_1210-MFG 2570,1580 r270 bottom value=4.7µF
C66 "DNP" FP-GCJ32DC72A475KE01L_1210-MFG 2915,1580 r270 bottom value=4.7µF
C67 "DNP" FP-GCJ32DC72A475KE01L_1210-MFG 3035,1580 r270 bottom value=4.7µF
C68 "DNP" 0603L 2660,1580 r90 bottom value=0.1uF
C69 "DNP" 0603L 2715,1580 r90 bottom value=0.1uF
C70 "DNP" 0603L 2770,1580 r90 bottom value=0.1uF
C71 "DNP" 0603L 2825,1580 r90 bottom value=0.1uF
C72 "KAF21KR72A474KU" 0805L 2380,1005 r0 top value=0.47uF
C73 "GRM155R71H103KA88D" 0402L 2660,1160 r0 top value=0.01uF
C74 "GRM155R71H103KA88D" 0402L 2280,1165 r0 top value=0.01uF
C75 "C0402C104K8RACAUTO" 0402L 2210,915 r90 top value=0.1uF
C76 "GRM188Z71A475ME15D" 0603L 2295,930 r0 top value=4.7uF
C77 "DNP" 0603L 2860,760 r270 top value=330pF
C78 "" 7343-31 4000,1150 r0 top value=220uF
C79 "" 7343-31 4000,1150 r0 bottom value=220uF
C80 "GRT32EC70J107ME13K" 1210L 3900,1440 r0 top value=100uF
C81 "GRT32EC70J107ME13K" 1210L 3900,1315 r0 top value=100uF
C82 "GRT32EC70J107ME13K" 1210L 3900,985 r0 top value=100uF
C83 "GRT32EC70J107ME13K" 1210L 3900,860 r0 top value=100uF
C84 "C0603C104K5RACTU" 0603L 4050,785 r90 top value=0.1uF
C85 "GRT32EC70J107ME13K" 1210L 3900,1440 r0 bottom value=100uF
C86 "GRT32EC70J107ME13K" 1210L 3900,1315 r0 bottom value=100uF
C87 "GRT32EC70J107ME13K" 1210L 3900,985 r0 bottom value=100uF
C88 "GRT32EC70J107ME13K" 1210L 3900,860 r0 bottom value=100uF
C89 "C0603C104K5RACTU" 0603L 4850,1260 r90 top value=0.1uF
C90 "C0402C104K8RACAUTO" 0402L 2210,1225 r270 top value=0.1uF
C91 "CGA2B1X7R1E333K050BC" 0402L 2075,1115 r90 top value=0.033uF
C92 "CGA2B1X7R1V224K050BC" 0402L 2660,885 r0 top value=0.22uF
C93 "CGA2B2NP01H220J050BA" 0402L 2030,895 r180 top value=22pF
C94 "DNP" 0402L 1970,915 r270 top value=5600pF
C95 "GRM155R72A271KA01D" 0402L 1995,1075 r90 top value=270pF
C96 "CRCW040210K0FKED" 0402L 2520,2365 r270 top value=10.0k
C97 "CRCW040210K0FKED" 0402L 2525,2085 r270 top value=10.0k
C98 "CRCW040210K0FKED" 0402L 2516,1264 r270 top value=10.0k
C99 "CRCW040210K0FKED" 0402L 2520,980 r270 top value=10.0k
C100 "GCJ32DC72A475KE01L" FP-GCJ32DC72A475KE01L_1210-MFG 3155,1580 r270 top value=4.7µF
C101 "GCJ32DC72A475KE01L" FP-GCJ32DC72A475KE01L_1210-MFG 3155,2675 r270 top value=4.7µF
C102 "DNP" FP-GCJ32DC72A475KE01L_1210-MFG 3155,1580 r270 bottom value=4.7µF
C103 "DNP" FP-GCJ32DC72A475KE01L_1210-MFG 3155,2675 r270 bottom value=4.7µF
D1 "BAT46WJ,115" SOD-323F 2325,2320 r0 top value=100V
D2 "TDZ5V6J,115" SOD-323 2665,2325 r0 bottom value=5.6V
D3 "SS10P4HM3_A/H" FP-SS10P4HM3_A/H_SMPC-MFG 4600,2205 r0 top value=40V
D4 "DNP" SOD-123 2260,2219 r180 bottom value=100V
D5 "BAT46WJ,115" SOD-323F 2325,1230 r0 top value=100V
D6 "TDZ5V6J,115" SOD-323 2665,1225 r0 bottom value=5.6V
D7 "SS10P4HM3_A/H" FP-SS10P4HM3_A/H_SMPC-MFG 4600,1195 r180 top value=40V
D8 "DNP" SOD-123 2277,1114 r180 bottom value=100V
D9 "DNP" SOD-523 2380,2200 r180 top value=30V
D10 "DNP" SOD-523 2410,1995 r180 top value=30V
D11 "DNP" SOD-523 2370,1120 r180 top value=30V
D12 "DNP" SOD-523 2410,895 r180 top value=30V
FID1 "Fiducial" Fiducial10-20 425,3200 r0 top
FID2 "Fiducial" Fiducial10-20 425,200 r0 top
FID3 "Fiducial" Fiducial10-20 4500,200 r0 top
FID4 "Fiducial" Fiducial10-20 425,200 r180 bottom
FID5 "Fiducial" Fiducial10-20 4500,200 r180 bottom
FID6 "Fiducial" Fiducial10-20 425,3200 r180 bottom
H1 "NY PMS 440 0025 PH" "NY PMS 440 0025 PH" 200,3200 r0 top locked
H2 "NY PMS 440 0025 PH" "NY PMS 440 0025 PH" 4750,3200 r0 top locked
H3 "NY PMS 440 0025 PH" "NY PMS 440 0025 PH" 200,200 r0 top locked
H4 "NY PMS 440 0025 PH" "NY PMS 440 0025 PH" 4750,200 r0 top locked
H5 "1902C" Keystone_1902C 200,3200 r180 bottom locked
H6 "1902C" Keystone_1902C 4750,3200 r180 bottom locked
H7 "1902C" Keystone_1902C 200,200 r180 bottom locked
H8 "1902C" Keystone_1902C 4750,200 r180 bottom locked
J1 "" Keystone_5102 1280,1950 r180 bottom
J2 "" Keystone_5102 600,1935 r180 bottom
J3 "+Vin_Main" Cinch_108-0902-001 15,2475 r0 bottom
J4 "+Vin_Main" Cinch_108-0902-001 15,2015 r0 bottom
J5 "GND_IN" Cinch_108-0903-001 15,1385 r0 bottom
J6 "GND_IN" Cinch_108-0903-001 15,925 r0 bottom
J7 "" Keystone_5102 600,1465 r180 bottom
J8 "EN1" TSW-102-07-G-S 1750,3200 r0 top
J9 "" Keystone_5102 3735,1700 r90 top
J10 "" Keystone_5102 3865,1700 r90 top
J11 "" Keystone_5102 3995,1700 r90 top
J12 "EN2" TSW-102-07-G-S 1750,200 r0 top
L1 "DNP" FP-XGL6060-102MEC_SMT2_6MM51_6MM71-MFG 1280,1950 r180 bottom value=1uH
L2 "DNP" TDK_ACM12V 600,1700 r0 bottom
L3 "DNP" MuRata_PLT10H 600,1700 r0 bottom value=2uH
L4 "XAL1010-152MEB" XAL1010 3200,2250 r0 top value=1.5uH
L5 "DNP" FP-VCUD128T-2R5MS8_SMT_IND_13MM3_12MM8-MFG 3200,2250 r0 top value=2.5uH
L6 "XAL1010-152MEB" XAL1010 3200,1150 r0 top value=1.5uH
L7 "DNP" FP-VCUD128T-2R5MS8_SMT_IND_13MM3_12MM8-MFG 3200,1150 r0 top value=2.5uH
LBL1 "THT-14-423-10" Label_650x200 950,200 r0 top
Logo1 "CE Mark" CE_Mark_5mm 1255,215 r180 bottom
Logo2 "FCC disclaimer" FCC_disclaimer 1020,50 r0 top
Logo3 "WEEE logo" WEEE_Minimum 915,281 r180 bottom
NT1 "Net-Tie" Net-Tie_10mil 3890,2620 r180 top net-tie
NT2 "Net-Tie" Net-Tie_10mil 2190,2110 r270 top net-tie
NT3 "Net-Tie" Net-Tie_10mil 1915,1875 r270 top net-tie
NT4 "Net-Tie" Net-Tie_10mil 3890,780 r180 top net-tie
NT5 "Net-Tie" Net-Tie_10mil 2190,1010 r270 top net-tie
R1 "CRCW25121R00JNEG" 2512 1560,3215 r270 bottom value=1.0
R2 "CRCW25121R00JNEG" 2512 1405,3215 r270 bottom value=1.0
R3 "CRCW04020000Z0EDHP" 0402L 2590,2260 r180 top value=0
R4 "CRCW04020000Z0EDHP" 0402L 2530,2250 r180 bottom value=0
R5 "DNP" FP-PML100HZPJV0L5_1225-MFG 3650,2380 r0 top value=500µ
R6 "CRCW0603150KFKEA" 0603L 2080,2305 r90 top value=150k
R7 "CRCW04020000Z0EDHP" 0402L 3625,2700 r180 top value=0
R8 "Y14830R00120F9R" FP-Y14830R00120F9R_2512-MFG 3650,2325 r0 top value=1.2m
R9 "CRCW04026K81FKED" 0402L 2030,2360 r270 top value=6.81k
R10 "DNP" 0402L 2350,2380 r0 top value=100k
R11 "DNP" 0603L 1965,2290 r180 top
R12 "CRCW040249R9FKED" 0402L 1975,2240 r180 top value=49.9
R13 "RMCF0402ZT0R00" "FP-RMCF0402ZT0R00_0402 (1005 metric)-0" 1940,2195 r180 top
R14 "DNP" 1210L 2755,1860 r0 top value=1.0
R15 "DNP" 0402L 2170,2335 r270 top value=0
R16 "DNP" 0402L 2035,2215 r90 top
R17 "CRCW060349R9FKEA" 0603L 3500,3200 r0 top value=49.9
R18 "CRCW040273K2FKED" 0402L 2030,2075 r180 top value=73.2k
R19 "DNP" 0402L 2085,2015 r270 top value=100k
R20 "" 0402L 2130,2335 r90 top value=0
R21 "CRCW04020000Z0EDHP" 0402L 2590,1980 r180 top value=0
R22 "DNP" 0402L 2240,1950 r270 top value=48.7k
R23 "RMCF0402FT100K" 0402L 2125,2015 r270 top value=100k
R24 "CRCW04023K01FKED" 0402L 2030,2035 r0 top value=3.01k
R25 "CRCW040254K9FKED" 0402L 2030,2115 r0 top value=54.9k
R26 "CRCW040219K1FKED" 0402L 2165,2015 r90 top value=19.1k
R27 "CRCW04020000Z0EDHP" 0402L 2585,1160 r180 top value=0
R28 "CRCW04020000Z0EDHP" 0402L 2530,1150 r180 bottom value=0
R29 "DNP" 0603L 2080,1205 r90 top value=100k
R30 "DNP" FP-PML100HZPJV0L5_1225-MFG 3650,1280 r0 top value=500µ
R31 "CRCW04020000Z0EDHP" 0402L 3625,1595 r0 top value=0
R32 "CRCW04020000Z0EDHP" 0402L 1975,2340 r0 top value=0
R33 "Y14830R00120F9R" FP-Y14830R00120F9R_2512-MFG 3650,1225 r0 top value=1.2m
R34 "DNP" 0402L 2030,1205 r270 top value=4.75k
R35 "RMCF0402FT100K" 0402L 2350,1290 r0 top value=100k
R36 "DNP" 0603L 1960,1190 r180 top
R37 "CRCW040249R9FKED" 0402L 1975,1140 r180 top value=49.9
R38 "RMCF0402ZT0R00" "FP-RMCF0402ZT0R00_0402 (1005 metric)-0" 1940,1095 r180 top
R39 "DNP" 1210L 2750,765 r0 top value=1.0
R40 "DNP" 0402L 2170,1205 r270 top value=0
R41 "DNP" 0402L 2035,1115 r90 top
R42 "DNP" 0603L 3500,200 r0 top value=49.9
R43 "CRCW04020000Z0EDHP" 0402L 2260,2380 r0 top value=0
R44 "CRCW040273K2FKED" 0402L 2025,975 r180 top value=73.2k
R45 "DNP" 0402L 2130,1205 r90 top value=0
R46 "DNP" 0402L 2085,915 r90 top value=100k
R47 "CRCW04020000Z0EDHP" 0402L 2590,885 r180 top value=0
R48 "DNP" 0402L 2030,935 r0 top value=7.50k
R49 "CRCW04020000Z0EDHP" 0402L 2030,1955 r0 top value=0
R50 "DNP" 0402L 2125,915 r270 top value=100k
R51 "DNP" 0402L 2240,850 r270 top value=0
R52 "CRCW040290K9FKED" 0402L 2025,1015 r0 top value=90.9k
R53 "" 0402L 2165,915 r270 top value=0
R54 "CRCW04023R32FKED" 0402L 2380,2250 r0 top value=3.32
R55 "CRCW04023R32FKED" 0402L 2410,2045 r0 top value=3.32
R56 "CRCW04023R32FKED" 0402L 2380,1170 r0 top value=3.32
R57 "CRCW04023R32FKED" 0402L 2405,945 r0 top value=3.32
R58 "DNP" 0402L 2565,2200 r180 bottom value=0
R59 "DNP" 0402L 2660,2250 r0 bottom value=0
R60 "DNP" 0402L 2555,1110 r180 bottom value=0
R61 "DNP" 0402L 2680,1155 r0 bottom value=0
R62 "" 0402L 2475,1110 r180 bottom value=0
R63 "" 0402L 2490,2200 r180 bottom value=0
R64 "DNP" FP-Y14830R00120F9R_2512-MFG 3650,2175 r0 top value=1.2m
R65 "DNP" FP-Y14830R00120F9R_2512-MFG 3650,1075 r0 top value=1.2m
R66 "DNP" FP-PML100HZPJV0L5_1225-MFG 3650,2120 r0 top value=500µ
R67 "DNP" FP-PML100HZPJV0L5_1225-MFG 3650,1020 r0 top value=500µ
SH-J1 "60900213421" Wurth_60900213421 6476,1819 r90 top
SH-J2 "60900213421" Wurth_60900213421 6246,1819 r90 top
T1 "Vout1" CB70-14-CY 4455,2700 r180 top
T2 "GND" CB70-14-CY 4450,1700 r180 top
T3 "Vout2" CB70-14-CY 4450,700 r180 top
TP1 "+Vin_Main" Testpoint_Keystone_Compact 150,2825 r180 bottom
TP2 "GND_In" Testpoint_Keystone_Compact 150,575 r180 bottom
TP3 "+VOUT1" Keystone5010 3700,3200 r0 top
TP4 "PG/SYNCOUT1" Keystone5012 2150,3200 r0 top
TP5 "SYNCIN1" Keystone5012 2550,3200 r0 top
TP6 "Bode1" Keystone5012 3300,3200 r0 top
TP7 "GND" Keystone5011 2900,200 r0 top
TP8 "GND" Keystone5011 2900,3200 r0 top
TP9 "+VOUT2" Keystone5010 3700,200 r0 top
TP10 "PG/SYNCOUT2" Keystone5012 2150,200 r0 top
TP11 "SYNCIN2" Keystone5012 2550,200 r0 top
TP12 "Bode2" Keystone5012 3300,200 r0 top
U1 "LMG3100R017" VBE0015A-MFG 2685,2400 r90 top
U2 "LM5148QPSQRGYRQ1" RGY0019B-MFG 2200,2155 r90 top
U3 "LMG3100R017" VBE0015A-MFG 2685,2120 r90 top
U4 "LMG3100R017" VBE0015A-MFG 2680,1300 r90 top
U5 "LM5148QPSQRGYRQ1" RGY0019B-MFG 2200,1055 r90 top
U6 "LMG3100R017" VBE0015A-MFG 2680,1020.28 r90 top

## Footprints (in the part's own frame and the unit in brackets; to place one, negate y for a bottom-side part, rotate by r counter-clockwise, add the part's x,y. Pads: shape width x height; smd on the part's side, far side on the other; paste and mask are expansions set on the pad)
0402L [mm] "0402 from SM-752 data"
  rect 0.6x0.5 smd: 1(-0.5,0) 2(0.5,0)
  body extent -0.55,-0.3 0.55,0.3, height 0.6
0603 [mm] "0603 from SM-752 data"
  rect 1x0.95 smd: 1(-0.8,0) 2(0.8,0)
  silkscreen extent -1.52,-0.69 1.52,0.69, body extent -0.87,-0.47 0.87,0.47, height 1
0603_HV [mil] "Ernesto recommended land pattern.  26 mil between pads."
  rect 30x30 smd: 1(-28,0) 2(28,0)
  silkscreen extent -52,-24 52,24, body extent -34,-19 34,19, height 39
0603L [mm] "0603 from SM-752 data"
  rect 0.8x0.85 smd: 1(-0.7,0) 2(0.7,0)
  silkscreen extent -0.07,-0.33 0.07,0.33, body extent -0.87,-0.47 0.87,0.47, height 1
0805_150 [mm] "0805 / 1.5 mm height"
  rect 1.15x1.45 smd: 1(-0.9,0) 2(0.9,0)
  silkscreen extent -0.1,-0.8 0.1,0.8, body extent -1.1,-0.72 1.1,0.72, height 1.5
0805L [mm] "0805 from SM-752 data"
  rect 1.1x1.4 smd: 1(-0.75,0) 2(0.75,0)
  body extent -1.1,-0.72 1.1,0.72, height 1.45
1206_180 [mm] "1206_180"
  rect 1.1x1.6 smd: 1(-1.7,0) 2(1.7,0)
  silkscreen extent -0.9,-1 0.9,1, body extent -1.75,-0.95 1.75,0.95, height 1.8
1210_220 [mm] "1210"
  rect 1.3x2.7 smd: 1(-1.45,0) 2(1.45,0)
  silkscreen extent -2.32,-1.57 2.32,1.57, body extent -1.7,-1.35 1.7,1.35, height 2.2
1210L [mm] "1210 from SM-752 data"
  rect 1.1x2.6 smd: 1(-1.35,0) 2(1.35,0)
  silkscreen extent -0.4,-1.2 0.4,1.2, body extent -1.7,-1.35 1.7,1.35, height 1.35
2512 [mm] "Chip Resistor, Body 6.3x3.2mm, IPC Medium Density"
  rect 1.3x3.4 smd: 1(-2.95,0) 2(2.95,0)
  silkscreen extent -1.9,-1.6 1.9,1.6, body extent -3.22,-1.67 3.22,1.67, height 0.71
7343-31 [mm] "Medium Density based on Kemet T495 dimensions"
  rect 2.55x2.45 smd: 1(-3.025,0) 2(3.025,0)
  silkscreen extent -4.56,-2.3 3.8,2.3, body extent -3.8,-2.3 3.8,2.3, height 3.1
CB70-14-CY [mil] "Terminal 90A Lug"
  rect 680x500 hole 254 copper offset -90,0 paste-99999: 1(0,0)
  body extent -1300,-260 250,260, height 714
CE_Mark_5mm [mil] "Minimum text height for CE Mark"
  silkscreen extent -138,-98 138,98
Cinch_108-0902-001 [mil] "Banana Jack Insul Nylon Red, TH"
  rrect2% 320x220 smd: 1(185,0)
  body extent -666,-219 272,219, height 232
Cinch_108-0903-001 [mil] "Banana Jack Insul Nylon Black, TH"
  rrect2% 320x220 smd: 1(185,0)
  body extent -666,-219 272,219, height 232
FCC_disclaimer [mil]
Fiducial10-20 [mm]
  round 1 smd mask+0.5: 1(0,0)
  Top Layer keep-out circle w1.178: c0,0 r0.5
FP-EEE-TP1K391V_SMT_CAP_17MM0_17MM0-MFG [mm]
  round 4.009 smd paste+0 mask+0: 1(-5.97,-0.048)
  round 4.105 smd paste+0 mask+0: 2(6,0)
  Top Layer region: -2.9,-1.4 -2.9,1.4 -4.2,1.4 -4.2,3.1 -7.8,3.1 -7.8,1.4 -9.7,1.4 -9.7,-1.4 -7.8,-1.4 -7.8,-3.1 -4.2,-3.1 -4.2,-1.4
  Top Layer region: 2.9,-1.4 2.9,1.4 4.2,1.4 4.2,3.1 7.8,3.1 7.8,1.4 9.7,1.4 9.7,-1.4 7.8,-1.4 7.8,-3.1 4.2,-3.1 4.2,-1.4
  silkscreen extent -10.37,-8.6 8.6,8.6, body extent -8.85,-8.5 8.85,8.5, height 17.1
FP-GCJ32DC72A475KE01L_1210-MFG [mm]
  rrect9% 1.1x2.05 smd paste+0 mask+0: 1(-1.65,0) 2(1.65,0)
  silkscreen extent -1.8,-1.4 1.8,1.4, body extent -2.3,-1.5 2.3,1.5, height 0.25
FP-PML100HZPJV0L5_1225-MFG [mm]
  rrect6% 1.7x6.4 smd paste+0 mask+0: 1(-1.25,0) 2(1.25,0)
  silkscreen extent -1.27,-3.63 1.27,3.63, body extent -2.2,-3.42 2.2,3.42, height 0.25
"FP-RMCF0402ZT0R00_0402 (1005 metric)-0" [mm]
  rrect20% 0.5x0.6 smd paste+0 mask+0: 1(-0.5,0) 2(0.5,0)
  body extent -0.85,-0.4 0.85,0.4, height 0.25
FP-SS10P4HM3_A/H_SMPC-MFG [mm]
  rrect8% 1.4x1.27 smd paste+0 mask+0: 1(1.04,-2.765) 2(-1.04,-2.765)
  rrect2% 4.8x4.72 smd paste+0 mask+0: 3(0,1.04)
  silkscreen extent -2.17,-3.08 2.17,-1.7, body extent -2.5,-3.5 2.5,3.5, height 0.25
FP-VCUD128T-2R5MS8_SMT_IND_13MM3_12MM8-MFG [mm]
  rrect3% 4x13.2 smd paste+0 mask+0: 1(-5.35,0) 2(5.35,0)
  silkscreen extent -8.51,-6.55 2.98,6.55, body extent -7.45,-6.7 7.45,6.7, height 0.25
FP-XGL6060-102MEC_SMT2_6MM51_6MM71-MFG [mm]
  rrect7% 1.43x5.5 smd paste+0 mask+0: 1(-2.02,0) 2(2.02,0)
  silkscreen extent -4.57,-3.45 3.35,3.45, body extent -3.25,-3.35 3.25,3.35, height 6.1
FP-Y14830R00120F9R_2512-MFG [mm]
  rrect6% 1.8x3.4 smd paste+0 mask+0: 1(-2.6,0) 2(2.6,0)
  silkscreen extent -0.25,-1.75 0.25,1.73, body extent -3.6,-1.85 3.6,1.85, height 0.25
Keystone5010 [mil] "Keystone Multipurpose loops"
  round 87 hole 63: 1(0,0)
  silkscreen extent -70,-70 70,70, body extent -63,-63 63,62, height 319
Keystone5011 [mil] "Keystone Multipurpose loops"
  round 87 hole 63: 1(0,0)
  silkscreen extent -70,-70 70,70, body extent -63,-63 63,62, height 319
Keystone5012 [mil] "Keystone Multipurpose loops"
  round 87 hole 63: 1(0,0)
  silkscreen extent -70,-70 70,70, body extent -63,-63 63,62, height 319
Keystone_1902C [mil] "Hex Standoff, 4-40 threaded, nylon"
  round 1 on Mech4: 0(0,0)
  body extent -145,-126 146,126, height 501
Keystone_5102 [mm] "Shorting Jumper, 5.375mm, 2 Position, SMT"
  rrect4% 2.475x3 smd: 1(-2.688,0) 2(2.688,0)
  body extent -3.42,-1.19 3.43,1.35, height 1
Label_650x200 [mil] "Thermal Transfer Label"
  round 1 on Mech13: 0(0,0)
  silkscreen extent -325,-100 325,100, body extent -325,-100 325,100, height 1
MuRata_PLT10H [mm] "SMD, 4-Leads, Body 12.9x6.6mm"
  rrect50% 1.5x2.6 smd: 1(-2.1,5.65) 2(2.1,5.65) 3(2.1,-5.65)
  rrect50% 1.5x2.61 smd: 4(-2.1,-5.65)
  silkscreen extent -3.61,-4.19 3.61,4.19, body extent -3.4,-6.7 3.4,6.7, height 9.4
Net-Tie_10mil [mil] "10mil net tie, no solder mask opening, no solder paste"
  rect 10x10 smd paste-5 mask-5: 1(-10,0) 2(10,0)
  Top Layer region: -6,5 6,5 6,-5 -6,-5
"NY PMS 440 0025 PH" [mm] "4-40 nylon screw and mounting hole"
  round 8 hole 3.2: 1(0,0)
  body extent -3.3,-3.3 3.3,3.3, height 2.69
RGY0019B-MFG [mm]
  rrect40% 0.25x0.6 smd paste+0 mask+0: 1(-0.75,2.15) 10(-0.75,-2.15) 11(0.75,-2.15) 19(0.75,2.15)
  rrect40% 0.6x0.25 smd paste+0 mask+0: 2(-1.65,1.75) 3(-1.65,1.25) 4(-1.65,0.75) 5(-1.65,0.25) 6(-1.65,-0.25) 7(-1.65,-0.75) 8(-1.65,-1.25) 9(-1.65,-1.75) 12(1.65,-1.75) 13(1.65,-1.25) 14(1.65,-0.25) 15(1.65,0.25) 16(1.65,0.75) 17(1.65,1.25) 18(1.65,1.75)
  rrect6% 1.7x2.3 smd paste-1000 mask+0: 20(0,0)
  silkscreen extent -1.8,-2.3 1.8,3.12, body extent -2.05,-2.55 2.05,2.55, height 0.25
SOD-123 [mm] "On Semi recommended land pattern"
  rect 0.915x1.22 smd: 1(-1.637,0) 2(1.637,0)
  silkscreen extent -2.74,-1.17 2.03,1.17, body extent -1.93,-0.9 1.93,0.9, height 1.35
SOD-323 [mm] "NXP recommended land pattern"
  rect 0.6x0.6 smd paste-0.05: 1(-1.1,0) 2(1.1,0)
  silkscreen extent -2.06,-0.86 1.53,0.86, body extent -1.3,-0.67 1.3,0.68, height 1.1
SOD-323F [mm] "NXP recommended land pattern"
  rect 0.6x0.6 smd paste-0.05: 1(-1.1,0) 2(1.1,0)
  silkscreen extent -2.06,-0.86 1.53,0.86, body extent -1.35,-0.67 1.35,0.68, height 0.79
SOD-523 [mm] "NXP Semiconductor recommended land pattern, nominal STEP model"
  rect 0.8x0.6 smd paste-0.05: 1(-0.55,0) 2(0.55,0)
  silkscreen extent -1.65,-0.66 1.2,0.66, body extent -0.8,-0.4 0.8,0.4, height 0.72
TDK_ACM12V [mm] "SMD, 4-Leads, Body 12x11mm, Pitch 5.2mm"
  rrect4% 3.2x2.7 smd: 1(-5.4,2.6) 2(-5.4,-2.6) 3(5.4,-2.6) 4(5.4,2.6)
  body extent -6,-5.5 6,5.5, height 5.55
Testpoint_Keystone_Compact [mil] "Compact SMT test point"
  rect 185x135 smd: 1(0,0)
  silkscreen extent -110,-80 110,80, body extent -75,-56 75,56, height 91
TSW-102-07-G-S [mm] "Samtec 100mil, 1x2, 230 mil above insulator"
  rrect50% 1.65x1.65 hole 1.016: 1(-1.27,0)
  round 1.65 hole 1.016: 2(1.27,0)
  silkscreen extent -3.17,-1.27 2.54,1.27, body extent -2.54,-1.27 2.54,1.27, height 8.38
VBE0015A-MFG [mm]
  round 0.265 smd paste+0 mask-1000: 1(-1.675,2.875) 11(1.675,2.875)
  rrect40% 0.7x0.25 smd paste+0 mask-1000: 2(-1.85,2.325) 3(-1.85,1.825) 4(-1.85,1.325) 5(-1.85,0.825) 8(1.85,1.325) 9(1.85,1.825) 10(1.85,2.325)
  rrect11% 1.9x3.95 smd paste-1000 mask-1000: 6(-1.3,-1.525) 7(1.3,-1.525)
  rrect40% 0.25x0.7 smd paste+0 mask-1000: 12(0.575,3.1) 13(0.075,3.1) 14(-0.425,3.1) 15(-0.925,3.1)
  Top Layer region: -2.15,2.7 -2.169,2.704 -2.185,2.715 -2.196,2.731 -2.2,2.75 -2.2,2.75 -2.2,2.9 -2.193,2.925 -2.175,2.943 -2.15,2.95 -2.15,2.95 -1.85,2.95 -1.812,2.958 -1.779,2.979 -1.758,3.012 -1.75,3.05 -1.75,3.05 -1.75,3.4 -1.746,3.419 -1.735,3.435 -1.719,3.446 -1.7,3.45 -1.7,3.45 -1.55,3.45 -1.531,3.446 -1.515,3.435 -1.504,3.419 -1.5,3.4 -1.5,3.4 -1.5,2.75 -1.504,2.731 -1.515,2.715 -1.531,2.704 -1.55,2.7 -1.55,2.7
  Top Layer region: 2.15,2.7 2.169,2.704 2.185,2.715 2.196,2.731 2.2,2.75 2.2,2.75 2.2,2.9 2.193,2.925 2.175,2.943 2.15,2.95 2.15,2.95 1.85,2.95 1.812,2.958 1.779,2.979 1.758,3.012 1.75,3.05 1.75,3.05 1.75,3.4 1.746,3.419 1.735,3.435 1.719,3.446 1.7,3.45 1.7,3.45 1.55,3.45 1.531,3.446 1.515,3.435 1.504,3.419 1.5,3.4 1.5,3.4 1.5,2.75 1.504,2.731 1.515,2.715 1.531,2.704 1.55,2.7 1.55,2.7
  silkscreen extent -2.92,-3.55 2.35,3.55, body extent -2.35,-3.6 2.35,3.55, height 0.25
WEEE_Minimum [mil] "WEEElie bin"
  silkscreen extent -95,-172 99,104
Wurth_60900213421 [mil] "Shunt, 2.54mm, Black"
  round 1 on Mech3: 0(0,0)
  body extent -98,-48 98,48, height 338
XAL1010 [mm] "COILCRAFT"
  rect 2.38x11.31 smd: 1(-3.325,0) 2(3.325,0)
  silkscreen extent -5.3,-6 5.3,6, body extent -5.25,-5.9 5.25,5.9, height 10

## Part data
C1: library part CMP-0048820-1, "Cap Aluminum Lytic 390uF 80V 20% (16 X 16.5mm) SMD 0.1 Ohm 1900mA 3000h 125°C Automotive T/R", Digikey Part Number=P123481CT-ND, Leakage Current=312uA, Manufacturer=Panasonic, Mouser Part Number=667-EEE-TP1K391V, Operating Temperature Range="-55°C to +125°C", Tolerance_%=20%, ValueDisplayed=390uF
C2 C3 C7 C8 C9: library part CMP-0084773-1, "CAP, CERM, 0.01 µF, 100 V,+/- 10%, X7R, AEC-Q200 Grade 1, 0603", Cap_Case=0603, Manufacturer=MuRata, TempCo=X7R, Tolerance_%=10%, Value2=100V, ValueDisplayed=0.01µF
C4: library part CMP-0008790-2, "CAP, CERM, 2.2 uF, 100 V, +/- 10%, X7S, AEC-Q200 Grade 1, 1206", Cap_Case=1206_180, Manufacturer=TDK, Supplier Part Number 1=445-6994-1-ND, TempCo=X7S, Tolerance_%=10%, Value1="0.005718 ohm", Value2=100V, ValueDisplayed=2.2uF
C5: library part CMP-0009134-2, "CAP, CERM, 4.7 uF, 100 V, +/- 10%, X7S, 1210", Cap_Case=1210_220, Manufacturer=TDK, Supplier Part Number 1=445-6042-1-ND, TempCo=X7S, Tolerance_%=10%, Value1="0.004236 ohm", Value2=100V, ValueDisplayed=4.7uF
C6: library part CMP-0009150-2, "CAP, CERM, 4.7 uF, 100 V, +/- 10%, X7S, AEC-Q200 Grade 1, 1210", Cap_Case=1210_220, Manufacturer=TDK, Supplier Part Number 1=445-7005-1-ND, TempCo=X7S, Tolerance_%=10%, Value1="0.004236 ohm", Value2=100V, ValueDisplayed=4.7uF
C10 C11: library part CMP-0861070-1, "CAP, CERM, 1 µF, 100 V,+/- 10%, X7R, AEC-Q200 Grade 1, 0805", Cap_Case=0805, Manufacturer=AVX, TempCo=X7R, Tolerance_%=10%, Value2=100V, ValueDisplayed=1µF
C12 C13 C14 C15 C16 C54 C55 C56 C57 C58 C100 C101: library part CMP-0093675-1, "4.7uF ±10% 100V Ceramic Capacitor X7S 1210 (3225 Metric)", Manufacturer=Murata, Operating Temperature Range="-55°C to +125°C", TempCo=22%, Temperature Characteristic=X7S, Tolerance_%=10%, ValueDisplayed=4.7uF
C17 C18 C19 C20 C59 C60 C61 C62: library part CMP-0064935-4, "CAP, CERM, 0.1 uF, 100 V,+/- 10%, X7R, AEC-Q200 Grade 1, 0603", Cap_Case=0603, Manufacturer=MuRata, Supplier Part Number 1=490-13420-1-ND, TempCo=X7R, Tolerance_%=10%, Value1=Unknown, Value2=100V, ValueDisplayed=0.1uF
C21 C22 C23 C24 C29 C63 C64 C65 C66 C67 C102 C103: library part CMP-0093675-1, "4.7uF ±10% 100V Ceramic Capacitor X7S 1210 (3225 Metric)", Manufacturer=Murata, Operating Temperature Range="-55°C to +125°C", Part Number=GCJ32DC72A475KE01L, TempCo=22%, Temperature Characteristic=X7S, Tolerance_%=10%, ValueDisplayed=4.7uF
C25 C26 C27 C28 C68 C69 C70 C71: library part CMP-0064935-4, "CAP, CERM, 0.1 uF, 100 V,+/- 10%, X7R, AEC-Q200 Grade 1, 0603", Cap_Case=0603, Manufacturer=MuRata, PartNumber=GCJ188R72A104KA01D, Supplier Part Number 1=490-13420-1-ND, TempCo=X7R, Tolerance_%=10%, Value1=Unknown, Value2=100V, ValueDisplayed=0.1uF
C30 C72: library part Capacitor, "CAP, CERM, xxxF, xxV, [TempCo], xx%, [PackageReference]", Alternate Manufacturer=-, Manufacturer="Kyocera AVX", Value1=100V
C31 C32 C73 C74: library part CMP-0006674-2, "CAP, CERM, 0.01 uF, 50 V, +/- 10%, X7R, 0402", Cap_Case=0402, Manufacturer=MuRata, Supplier Part Number 1=490-4516-1-ND, TempCo=X7R, Tolerance_%=10%, Value1=Unknown, Value2=50V, ValueDisplayed=0.01uF
C33 C48 C75 C90: library part CMP-0079150-1, "CAP, CERM, 0.1 µF, 10 V,+/- 10%, X7R, AEC-Q200 Grade 1, 0402", Cap_Case=0402, Manufacturer=Kemet, Supplier Part Number 1=399-15984-1-ND, TempCo=X7R, Tolerance_%=10%, Value2=10V, ValueDisplayed=0.1µF
C34 C76: library part CMP-0007498-4, "CAP, CERM, 4.7 uF, 10 V, +/- 20%, X7R, 0603", Cap_Case=0603, Manufacturer=MuRata, TempCo=X7R, Tolerance_%=20%, Value1=Unknown, Value2=10V, ValueDisplayed=4.7uF
C35 C77: library part Capacitor, "CAP, CERM, 330F, 100V, C0G, 5%, 0603", Alternate Manufacturer=-, Manufacturer=Murata, PartNumber=GCM1885C2A331JA16D, Value1=100V
C36 C37 C78 C79: library part CMP-0012661-3, "CAP, Tantalum Polymer, 220 uF, 10 V, +/- 20%, 0.025 ohm, AEC-Q200 Grade 1, 7343-31 SMD", Cap_Case=7.3x4.3x3.1mm, Manufacturer=Kemet, PartNumber=T598D227M010ATE025, Supplier Part Number 1=399-12102-1-ND, Tolerance_%=20%, Value1="0.025 ohm", Value2=10V, ValueDisplayed=220uF
C38 C39 C40 C41 C43 C44 C45 C46 C80 C81 C82 C83 C85 C86 C87 C88: library part Capacitor, "CAP, CERM, 100uF, 6.3V, X7S, 20%, 1210", Alternate Manufacturer=-, Manufacturer=Murata, Value1=6.3V
C42 C84 C89: library part CMP-0006861-4, "CAP, CERM, 0.1 uF, 50 V, +/- 10%, X7R, 0603", Cap_Case=0603, Manufacturer=Kemet, Supplier Part Number 1=399-5089-1-ND, TempCo=X7R, Tolerance_%=10%, Value1=Unknown, Value2=50V, ValueDisplayed=0.1uF
C47: library part CMP-0006861-4, "CAP, CERM, 0.1 uF, 50 V, +/- 10%, X7R, 0603", Cap_Case=0603, Manufacturer=Kemet, PartNumber=C0603C104K5RACTU, Supplier Part Number 1=399-5089-1-ND, TempCo=X7R, Tolerance_%=10%, Value1=Unknown, Value2=50V, ValueDisplayed=0.1uF
C49 C91: library part CMP-0006306-2, "CAP, CERM, 0.033 uF, 25 V, +/- 10%, X7R, AEC-Q200 Grade 1, 0402", Cap_Case=0402, Manufacturer=TDK, Supplier Part Number 1=445-12247-1-ND, TempCo=X7R, Tolerance_%=10%, Value1=Unknown, Value2=25V, ValueDisplayed=0.033uF
C50 C92: library part Capacitor, "CAP, CERM, 0.22uF, 35V, X7R, 10%, 0402", Alternate Manufacturer=-, Manufacturer=TDK, Value1=35V
C51 C93: library part CMP-0006311-2, "CAP, CERM, 22 pF, 50 V, +/- 5%, C0G/NP0, AEC-Q200 Grade 1, 0402", Cap_Case=0402, Manufacturer=TDK, Supplier Part Number 1=445-12130-1-ND, TempCo=C0G/NP0, Tolerance_%=5%, Value1=Unknown, Value2=50V, ValueDisplayed=22pF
